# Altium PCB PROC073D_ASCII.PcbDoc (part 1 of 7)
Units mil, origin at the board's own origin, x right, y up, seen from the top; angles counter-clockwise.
Board outline 2165.35 x 2695.12 mil, 8 copper layers (Top Layer, L2_GND, L3_SIGNAL 1, L4_SIGNAL 2, L5_SIGNAL 3, L6_SIGNAL 4, L7_GND, Bottom Layer), stack 56.1 mil thick; 414 components, 319 nets, 1353 pads, 1669 vias.
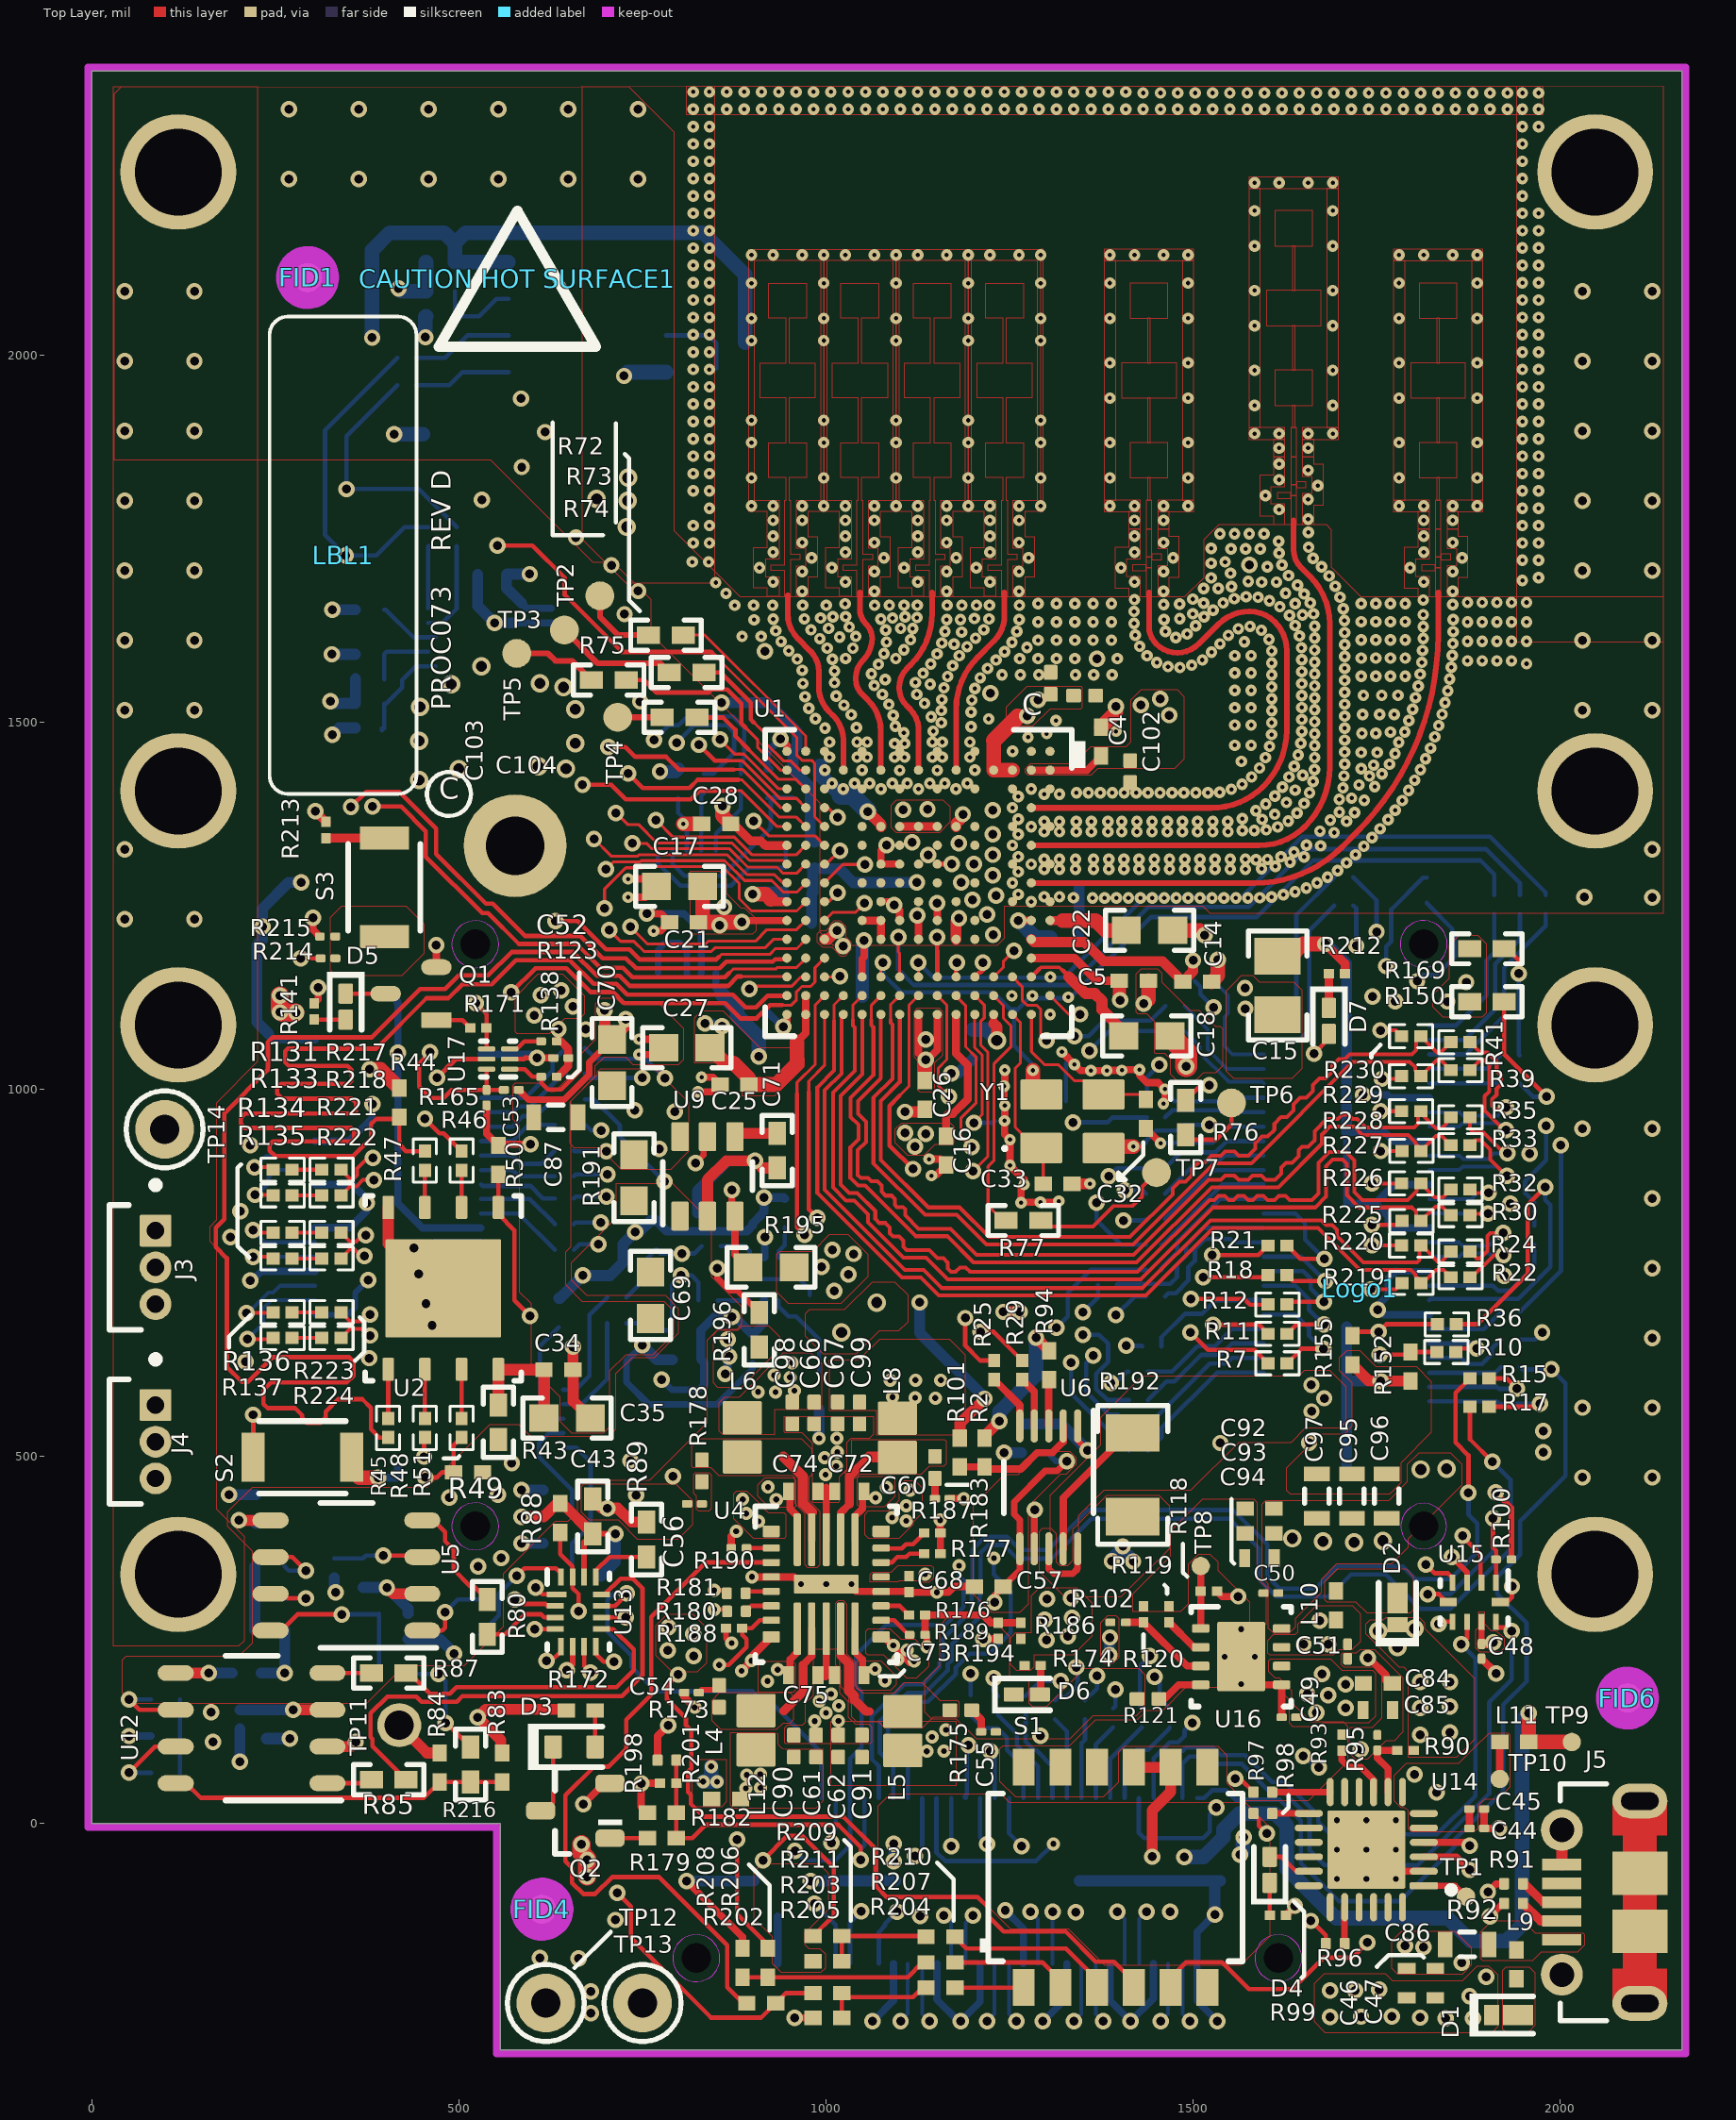
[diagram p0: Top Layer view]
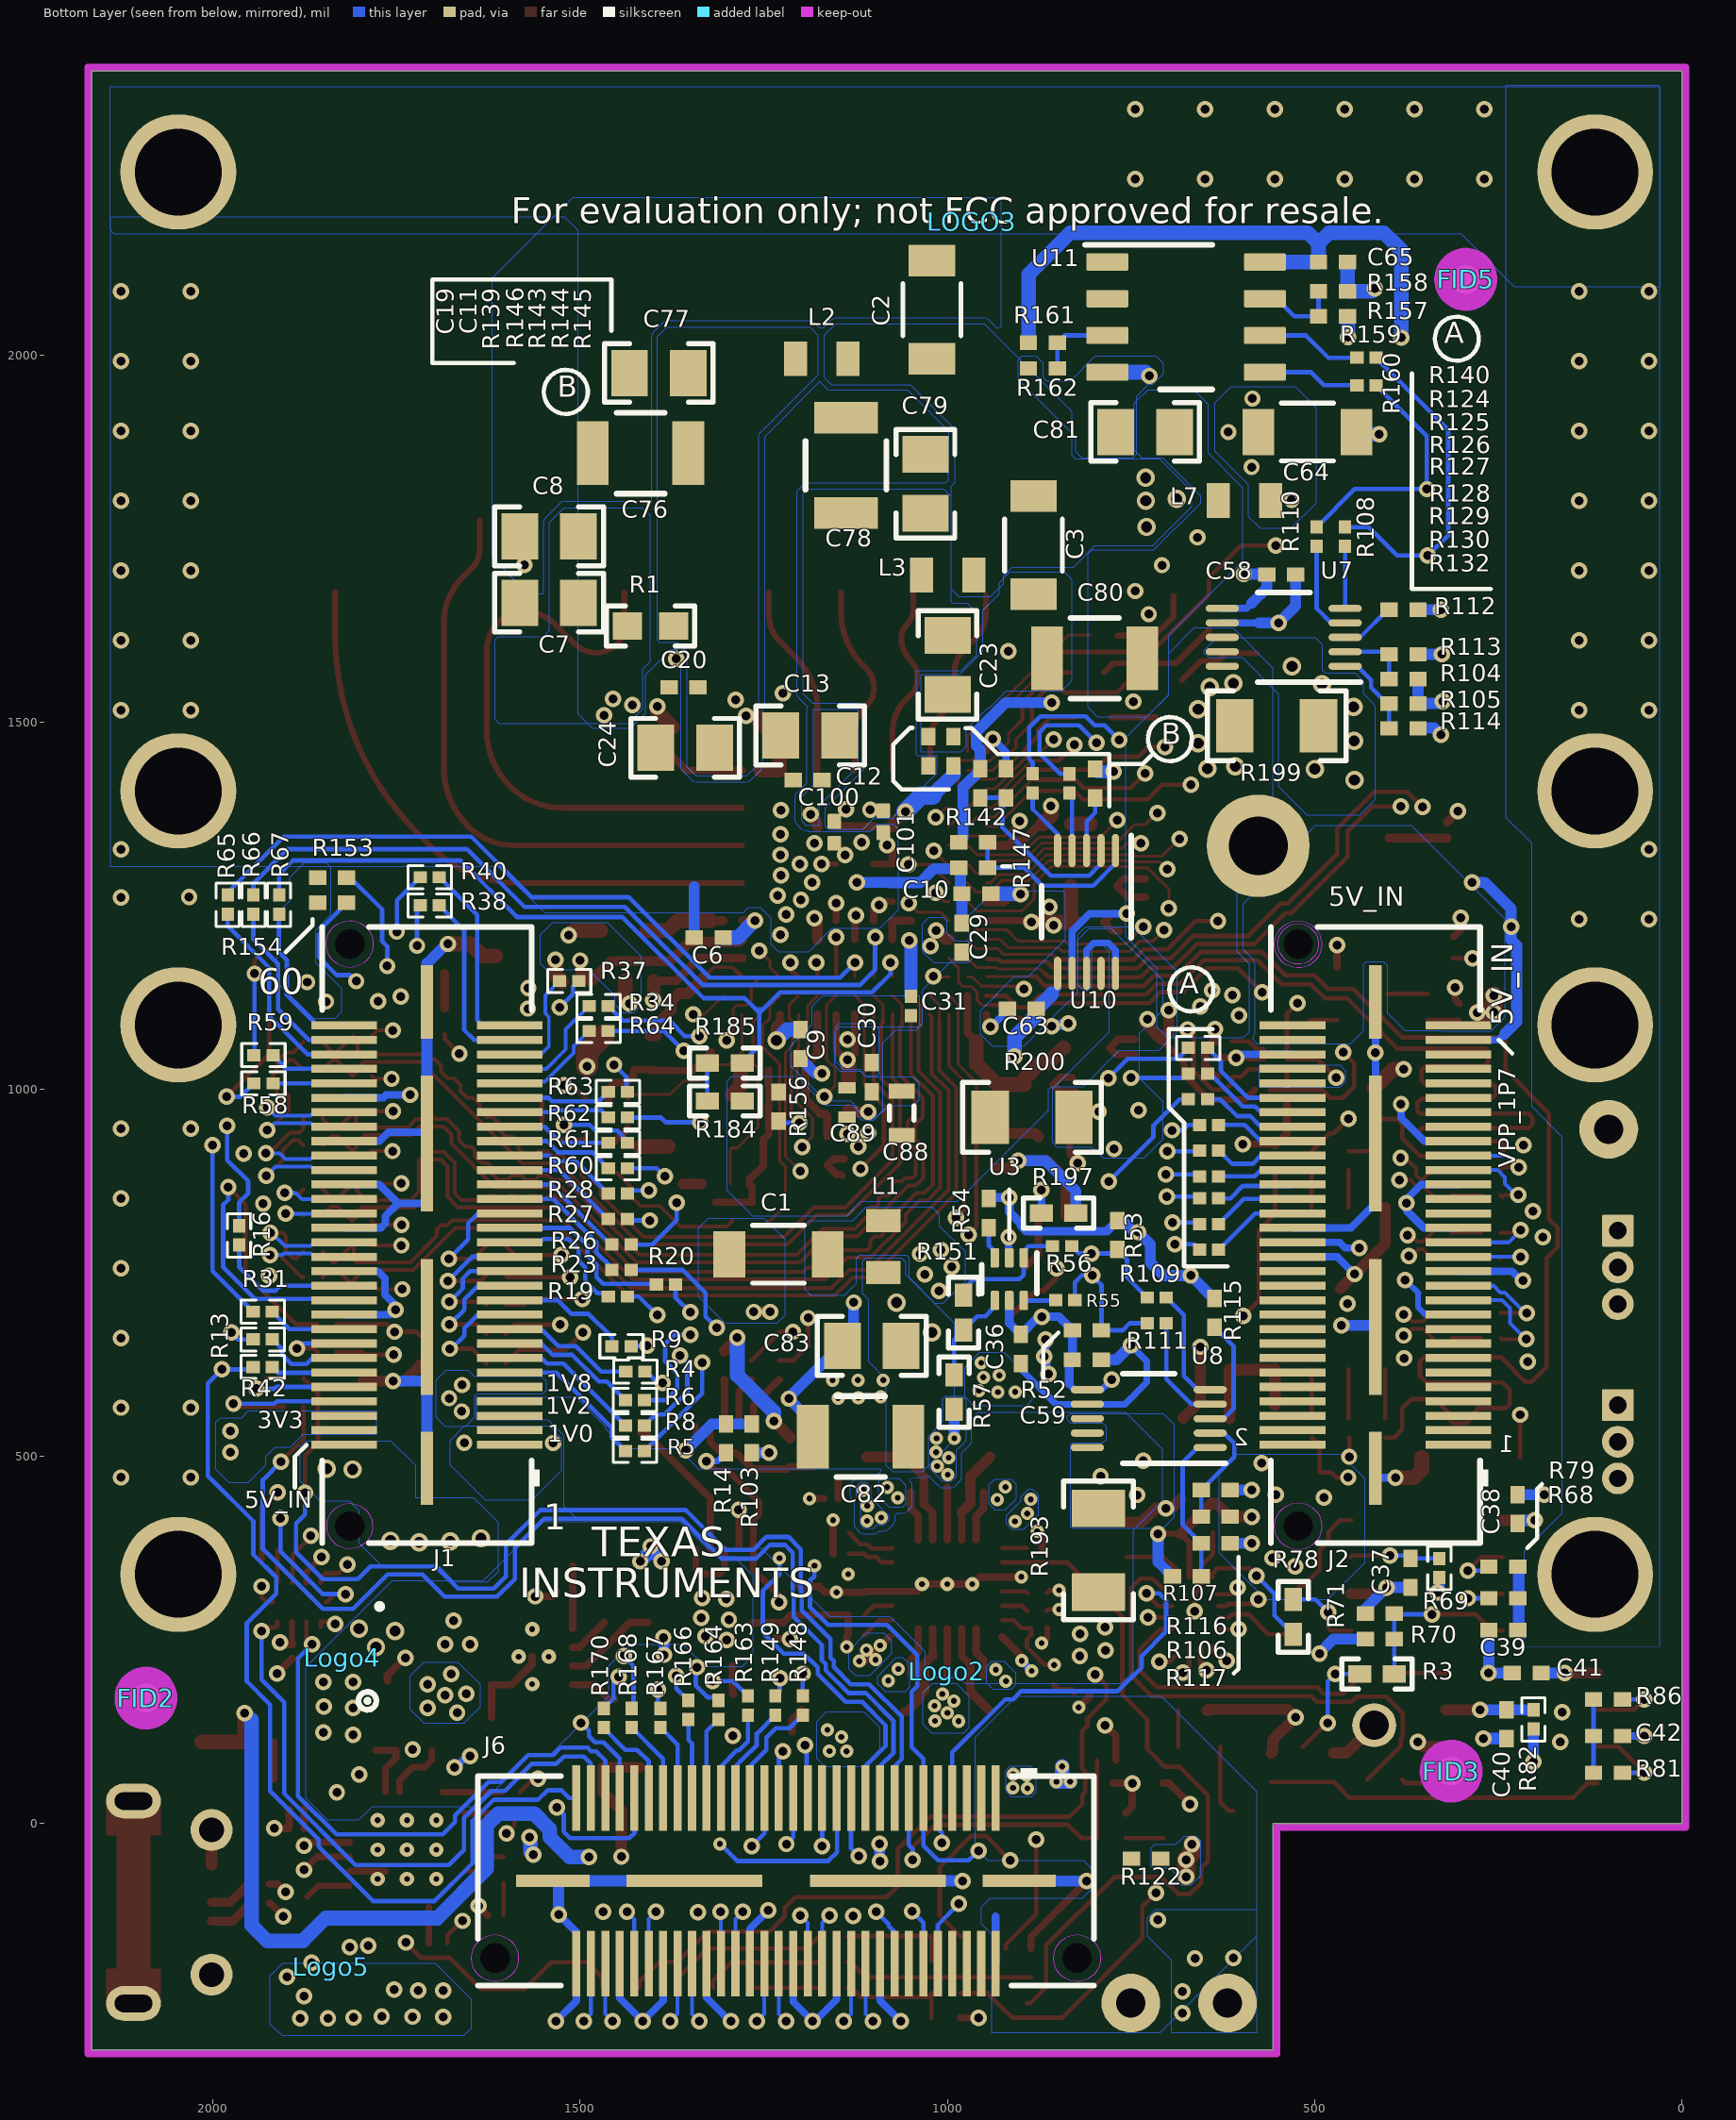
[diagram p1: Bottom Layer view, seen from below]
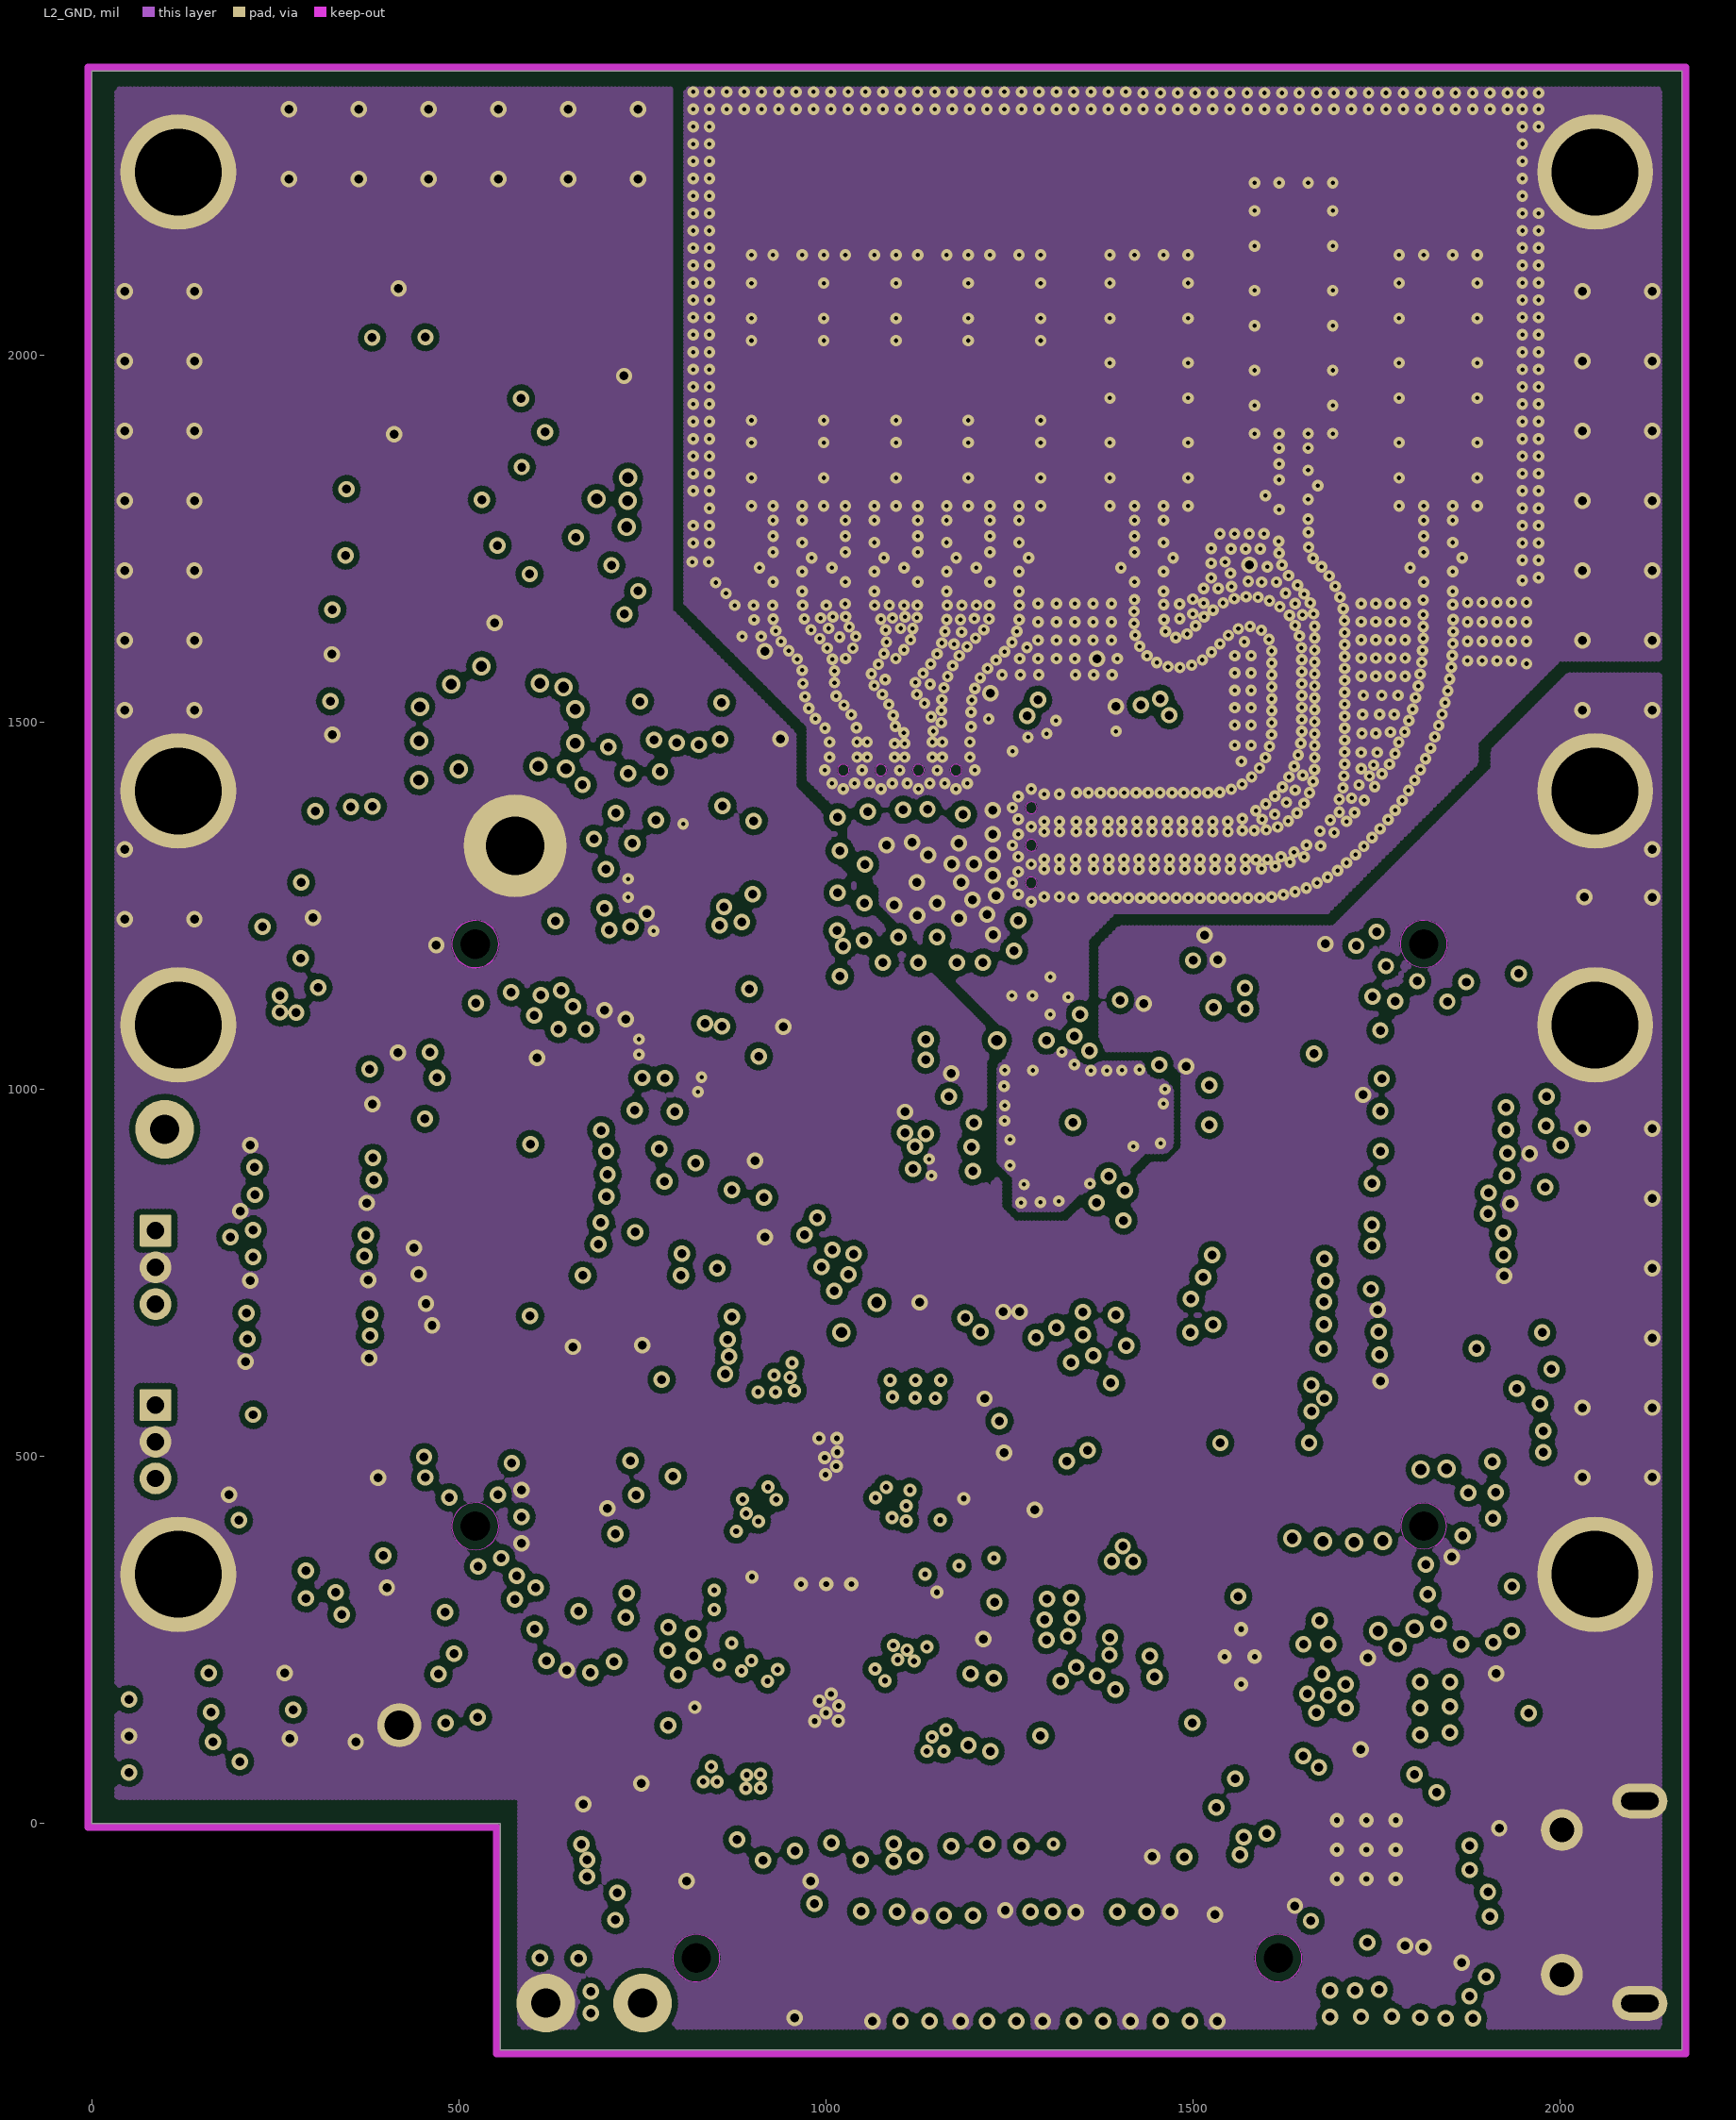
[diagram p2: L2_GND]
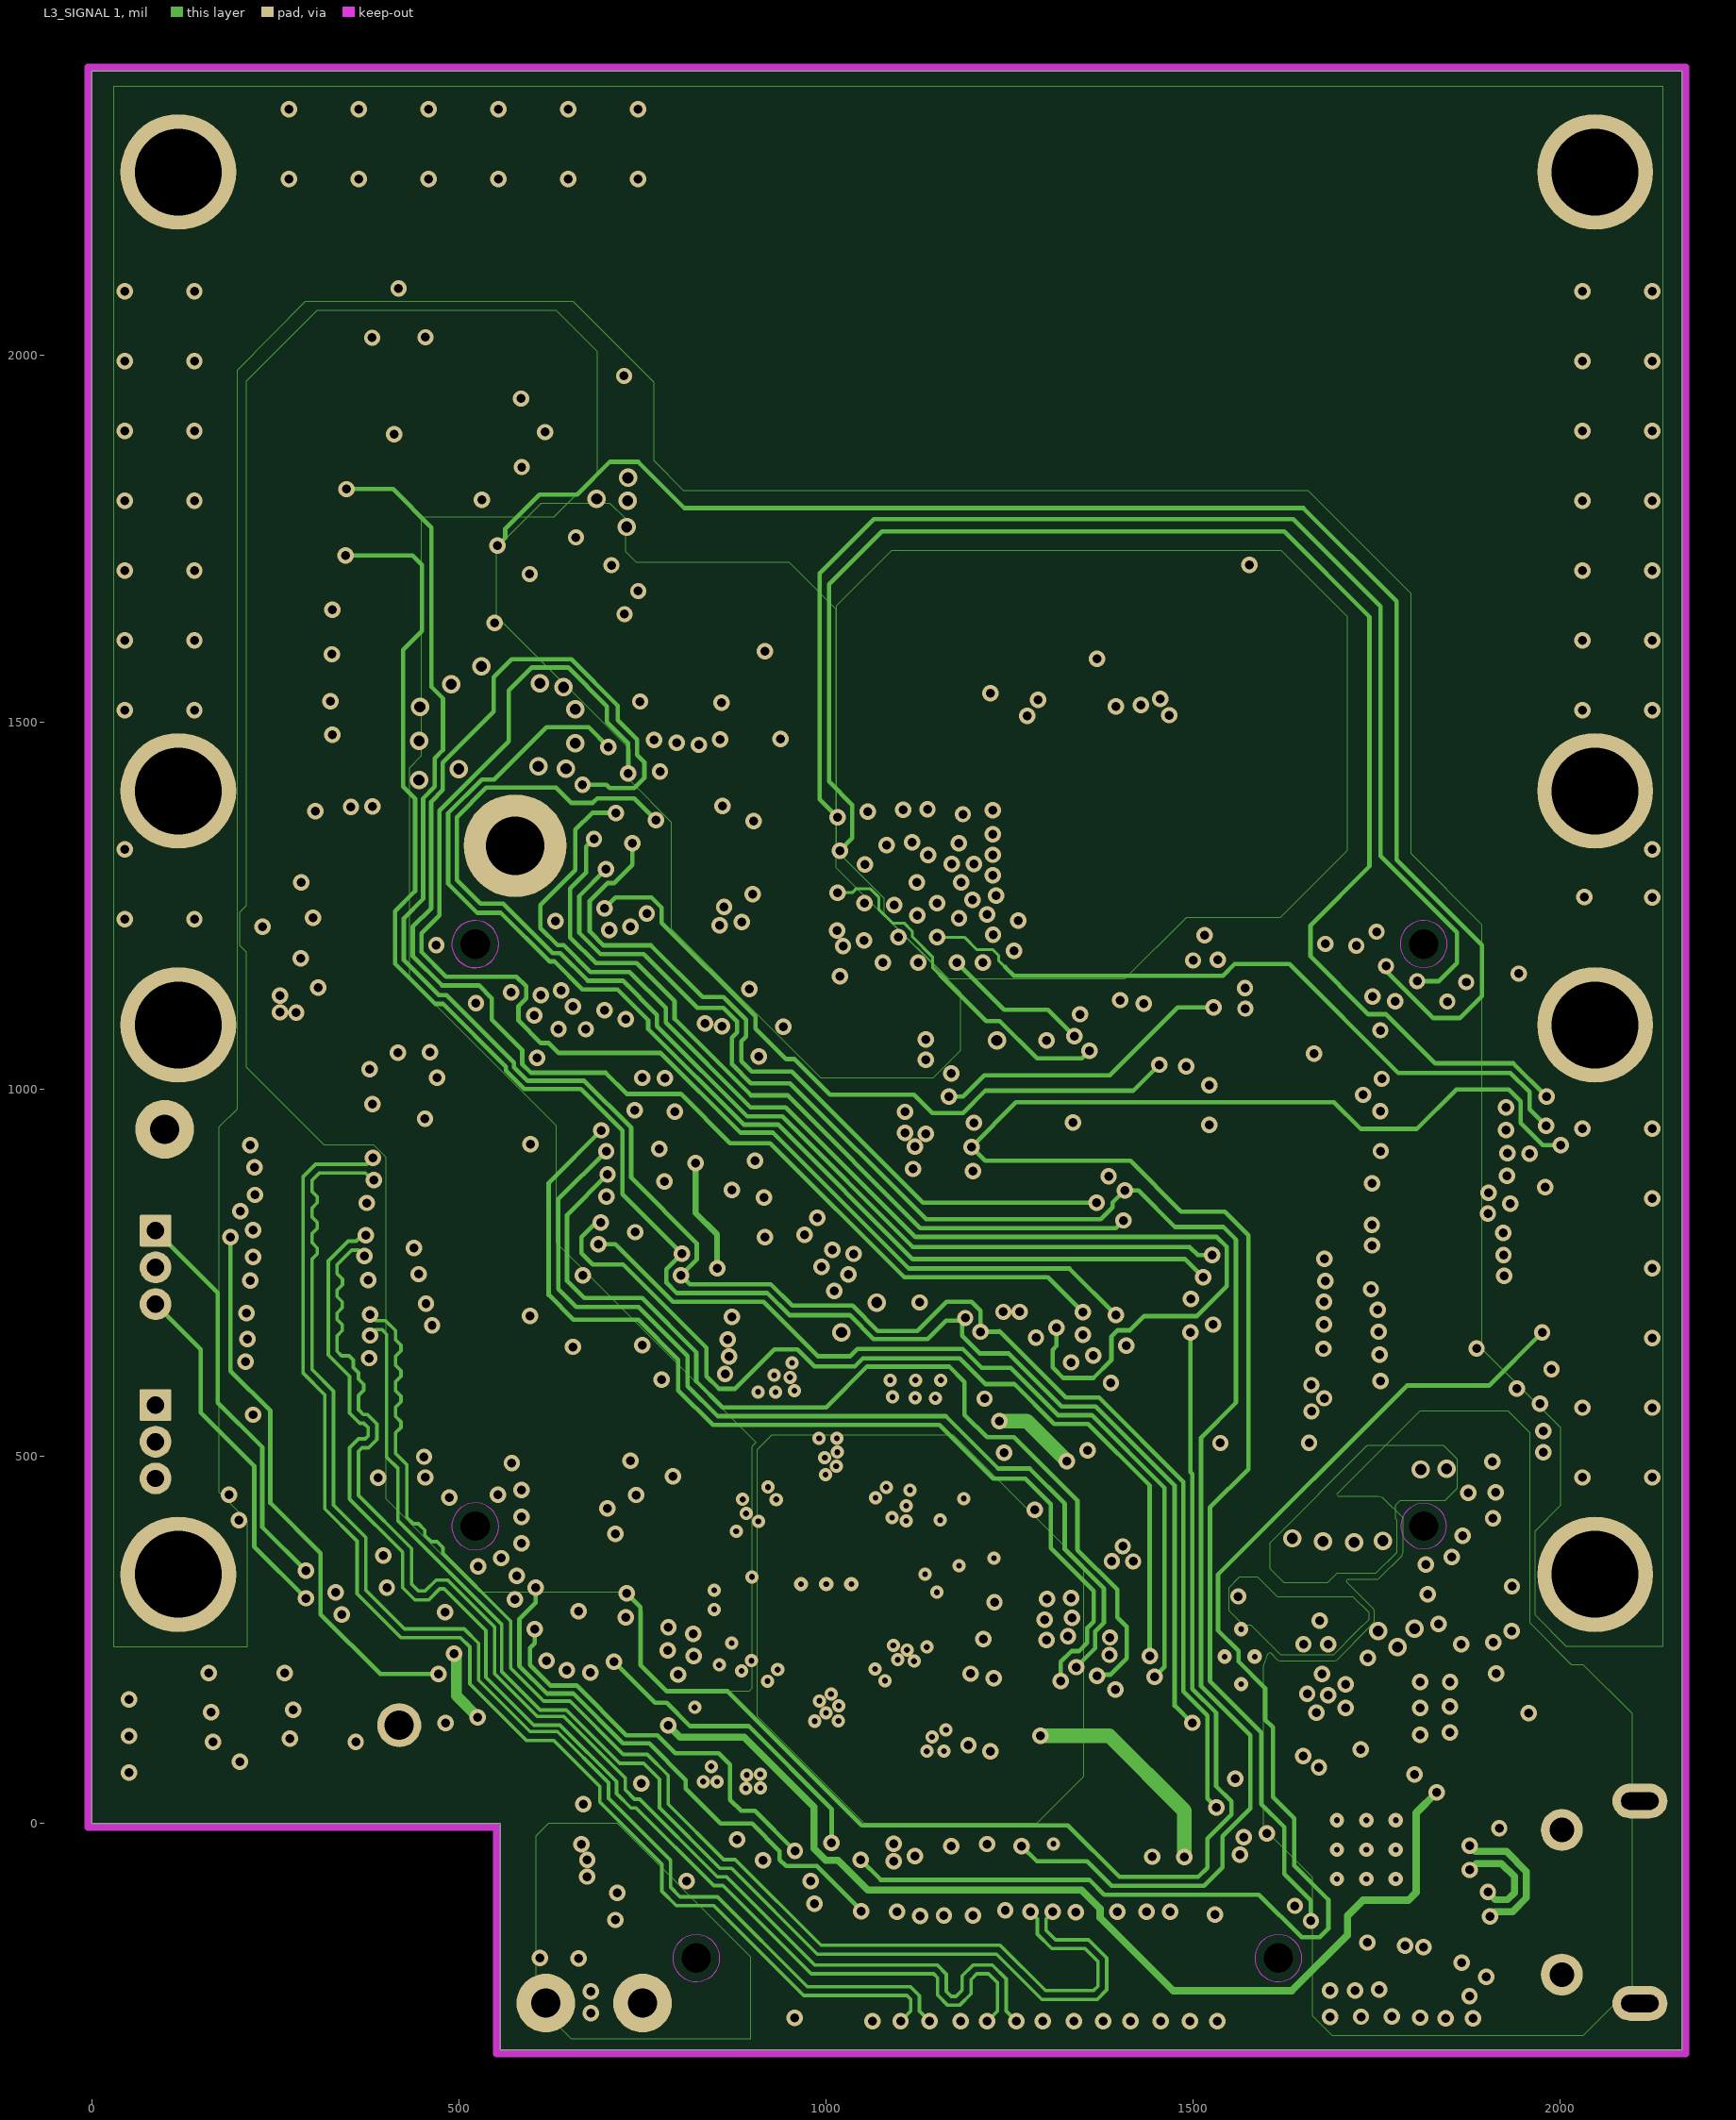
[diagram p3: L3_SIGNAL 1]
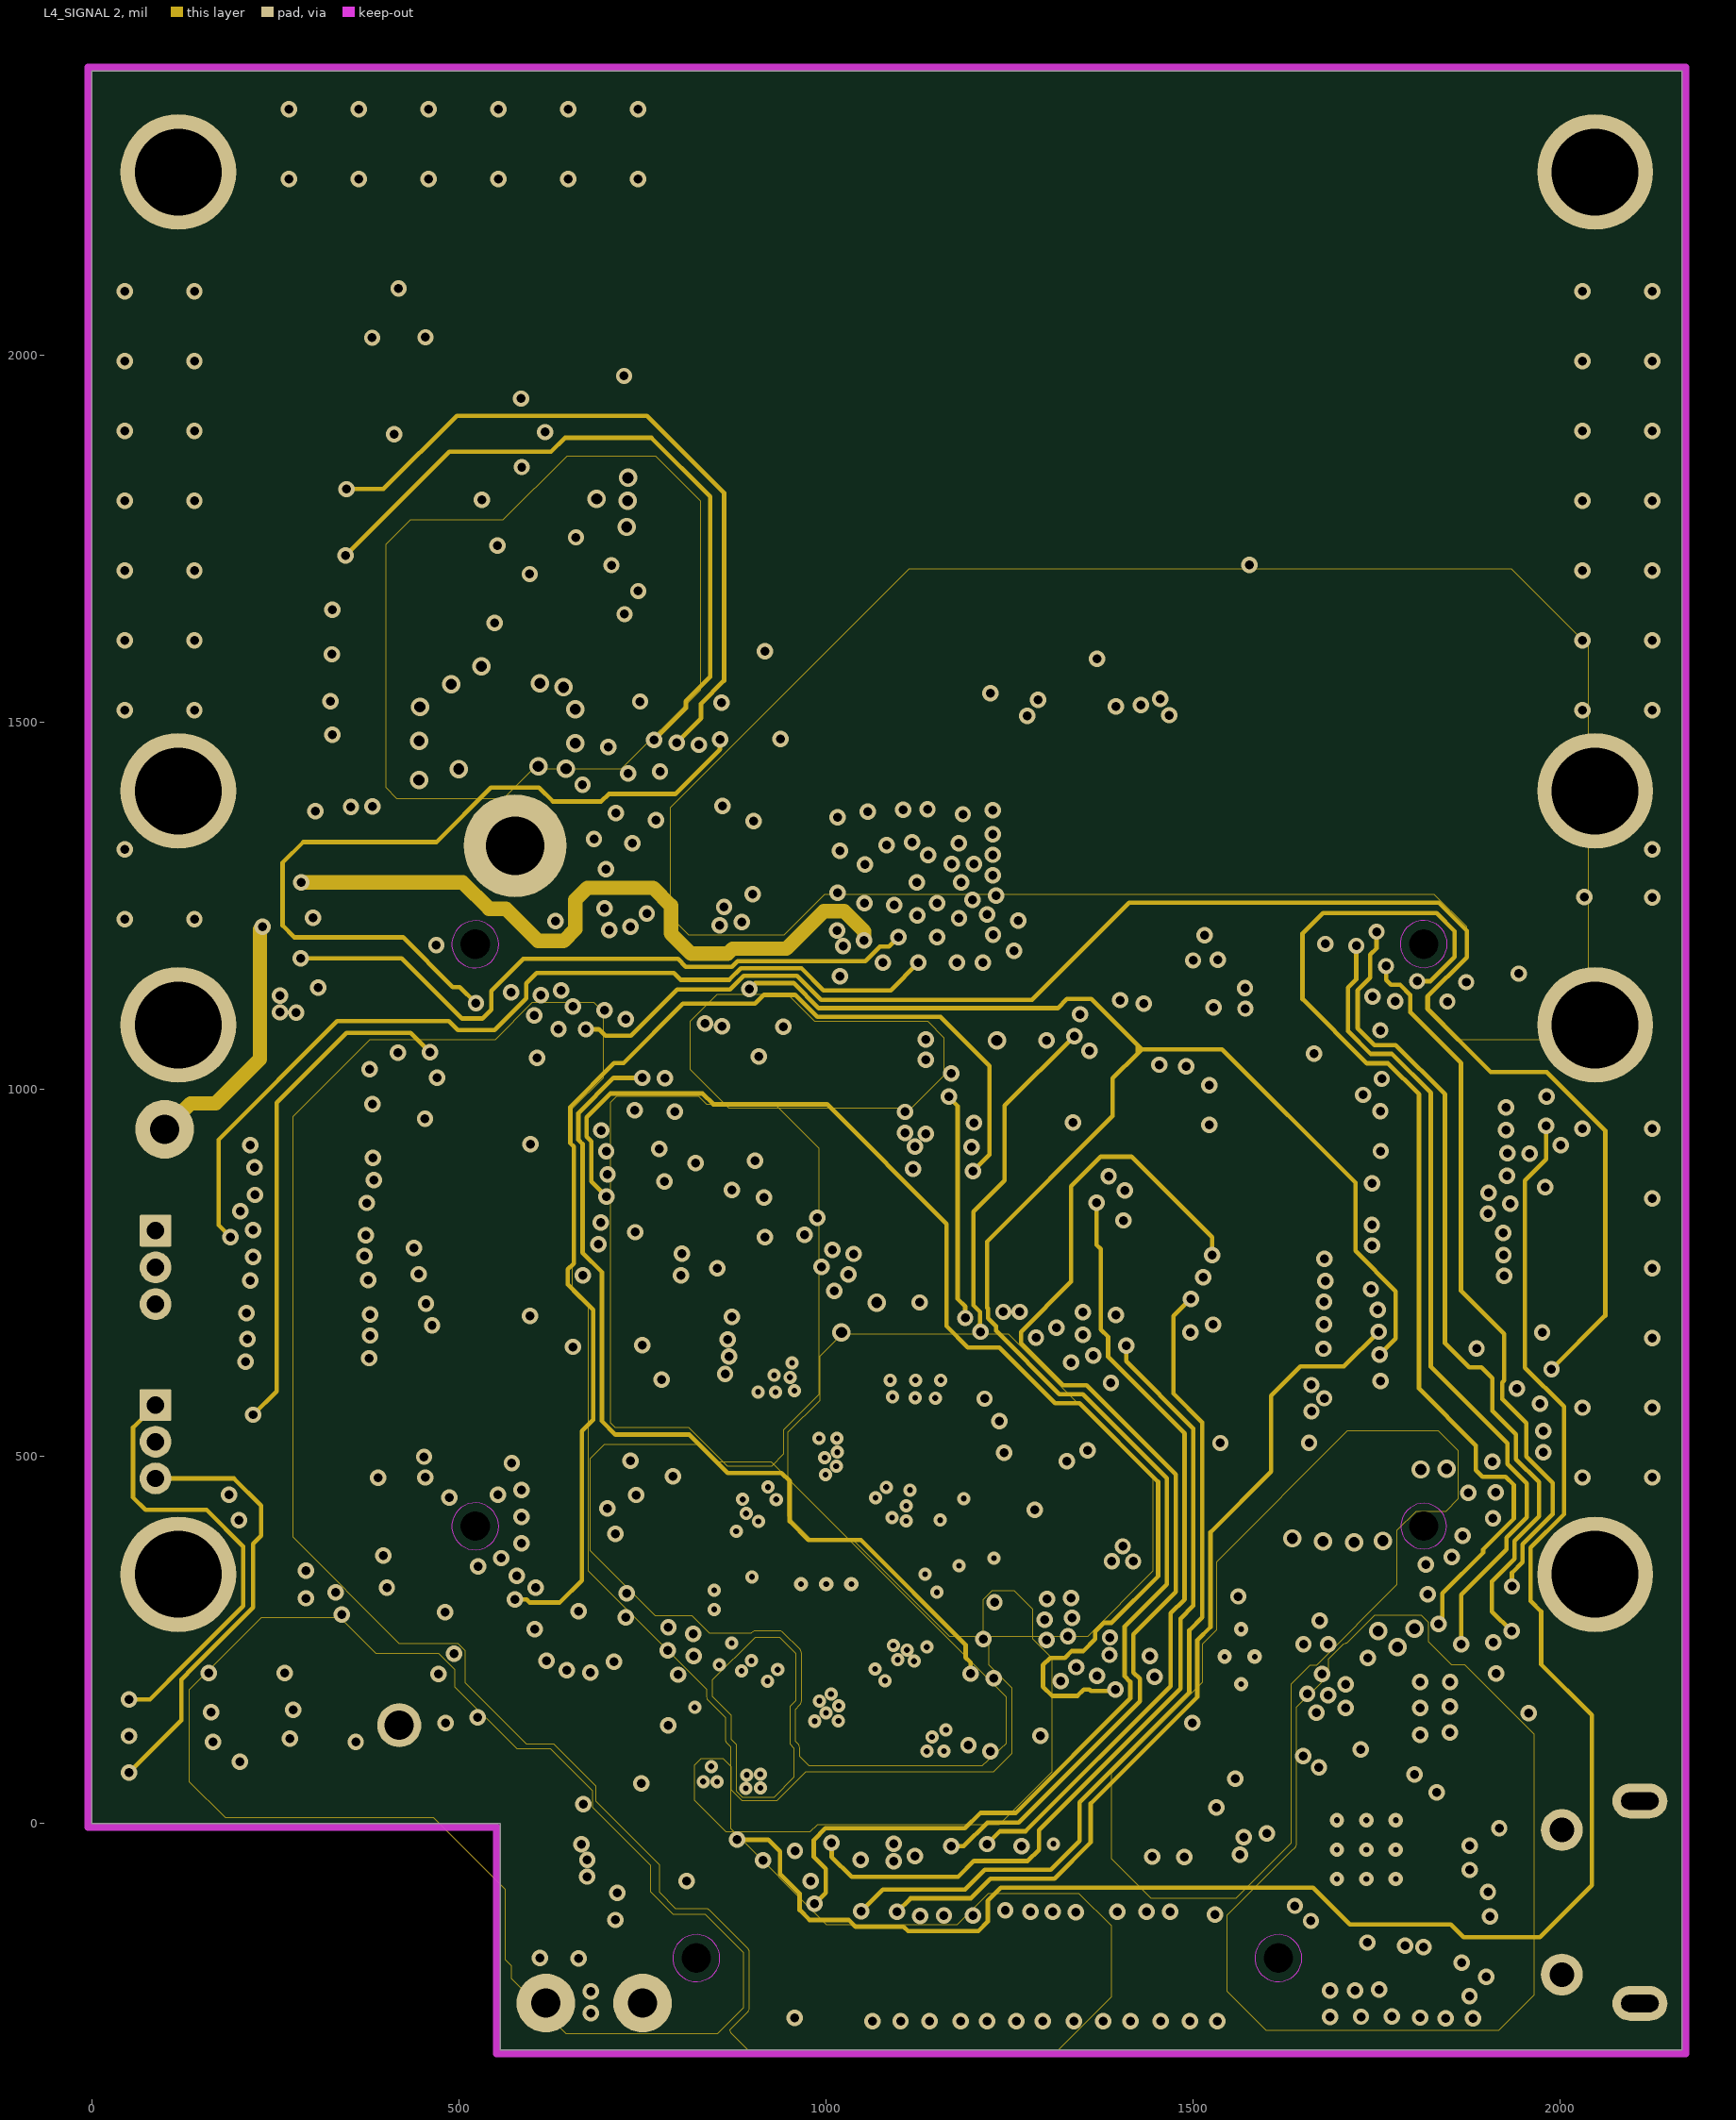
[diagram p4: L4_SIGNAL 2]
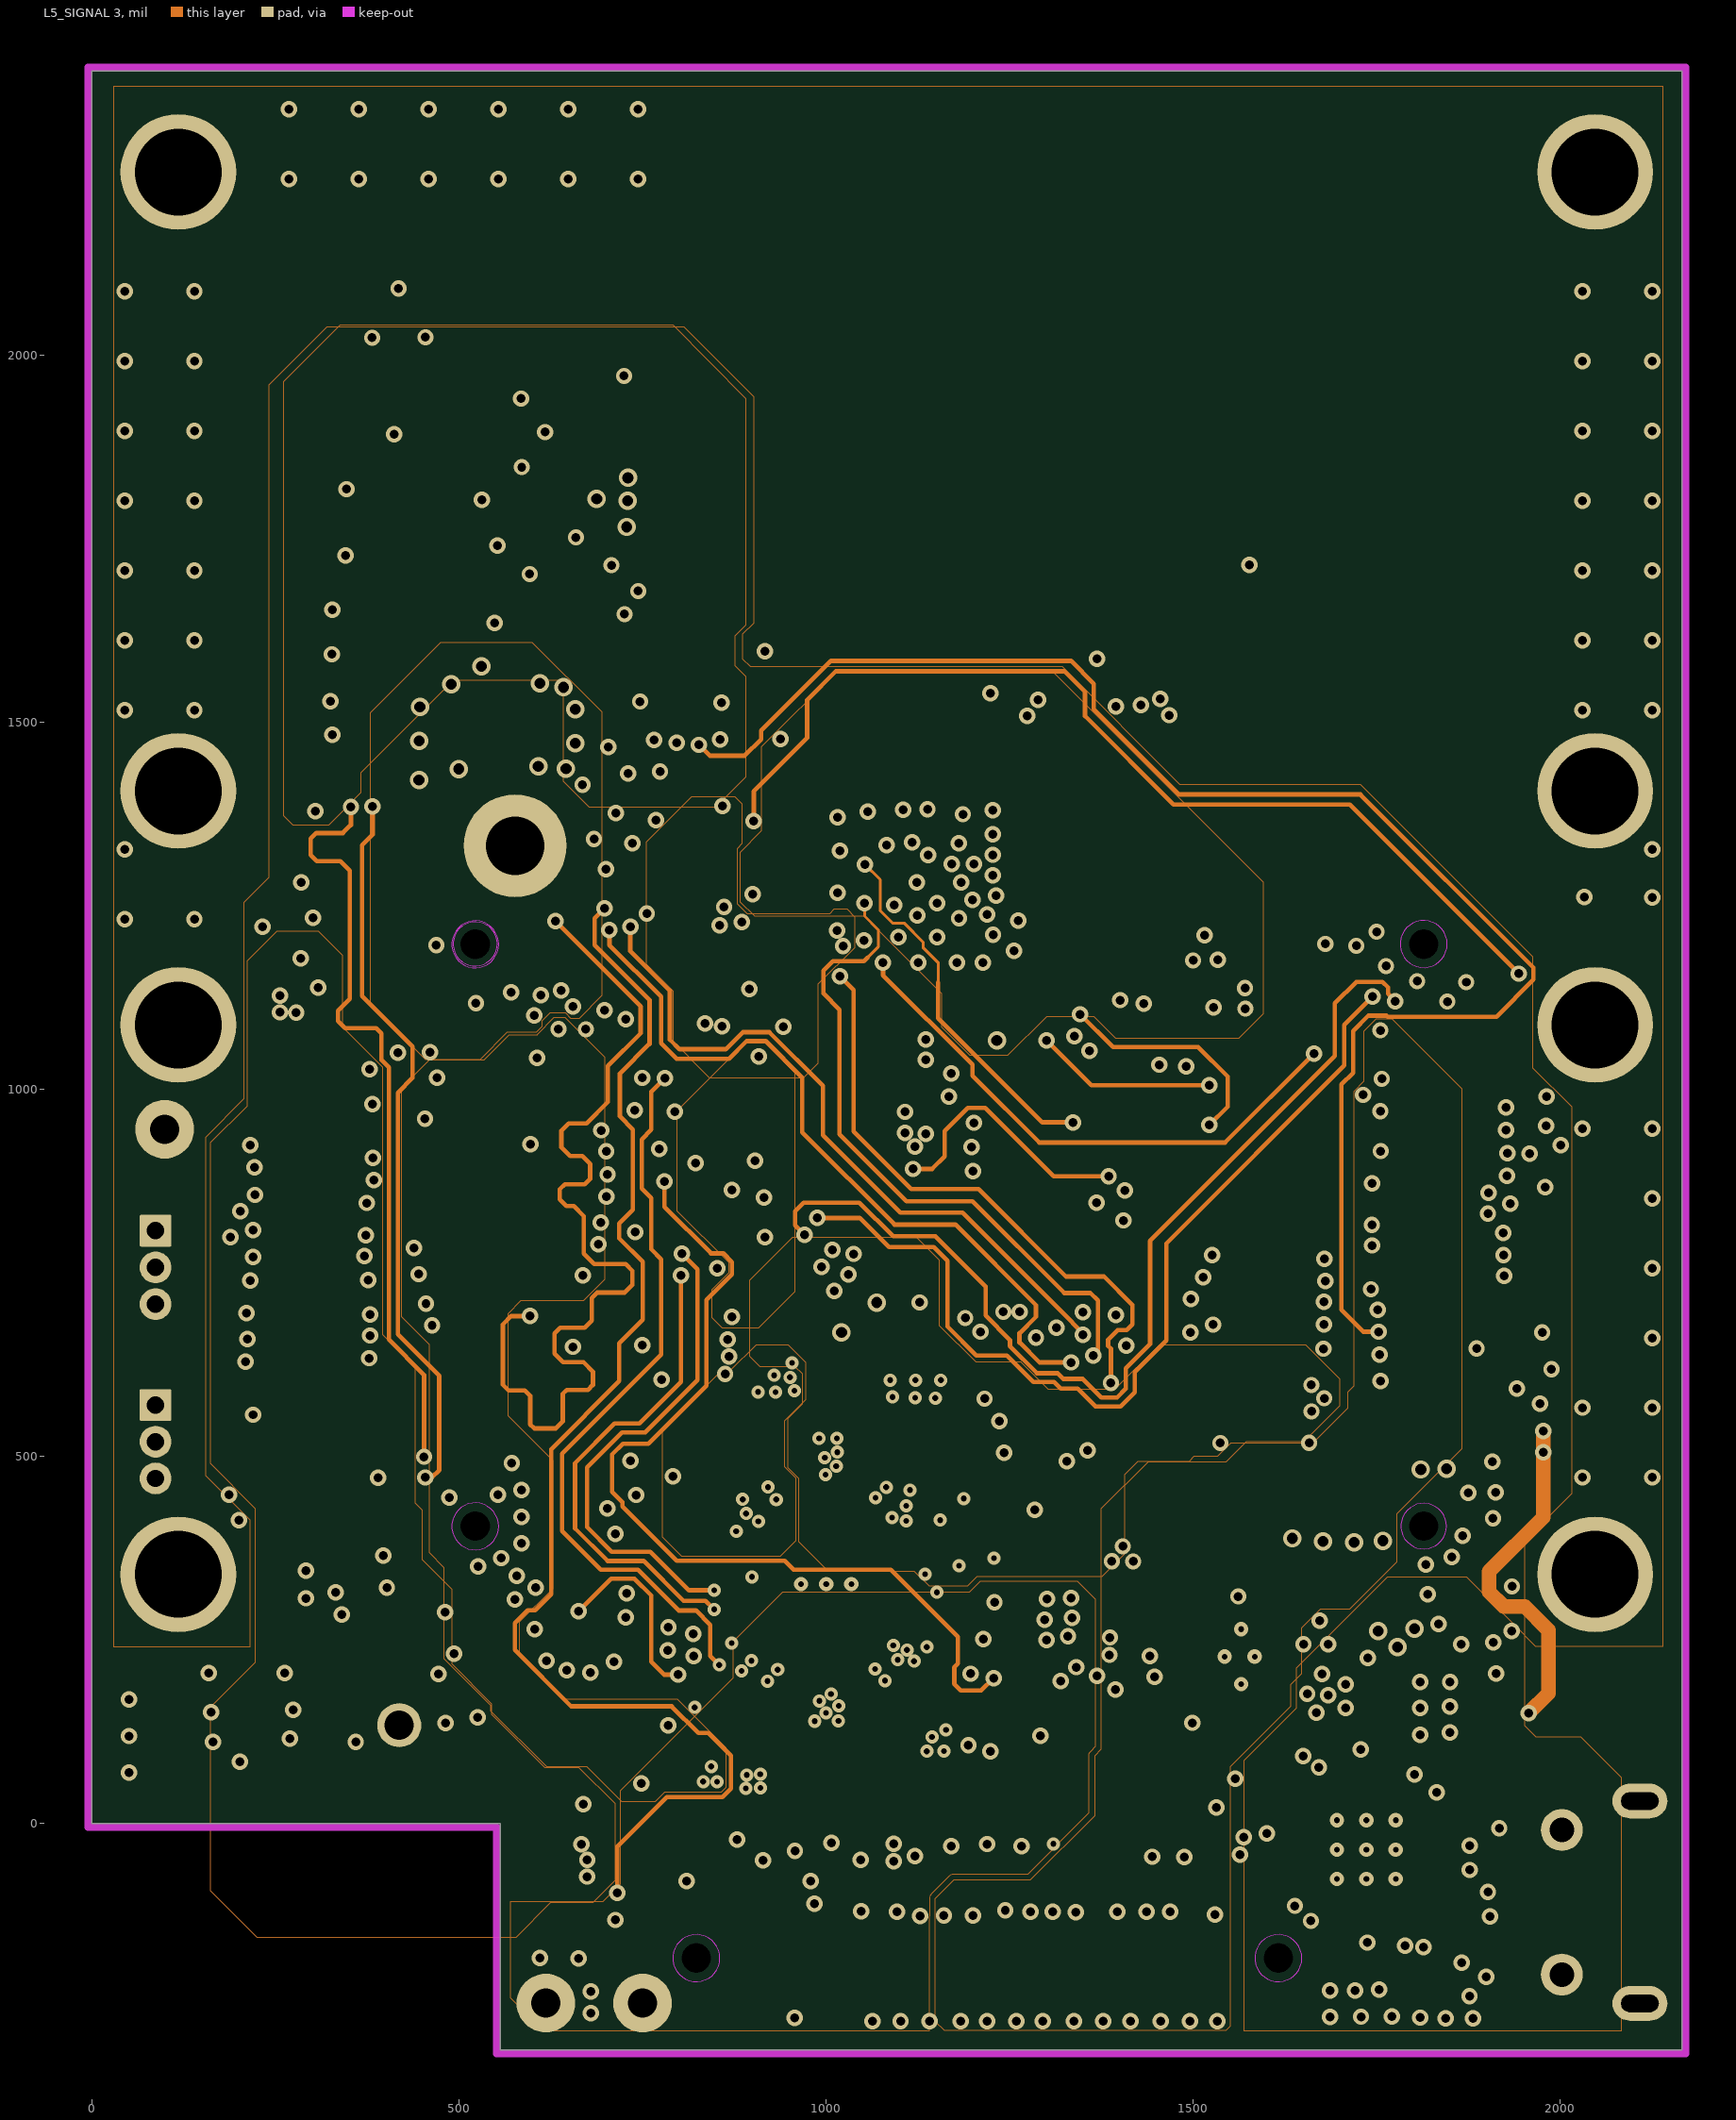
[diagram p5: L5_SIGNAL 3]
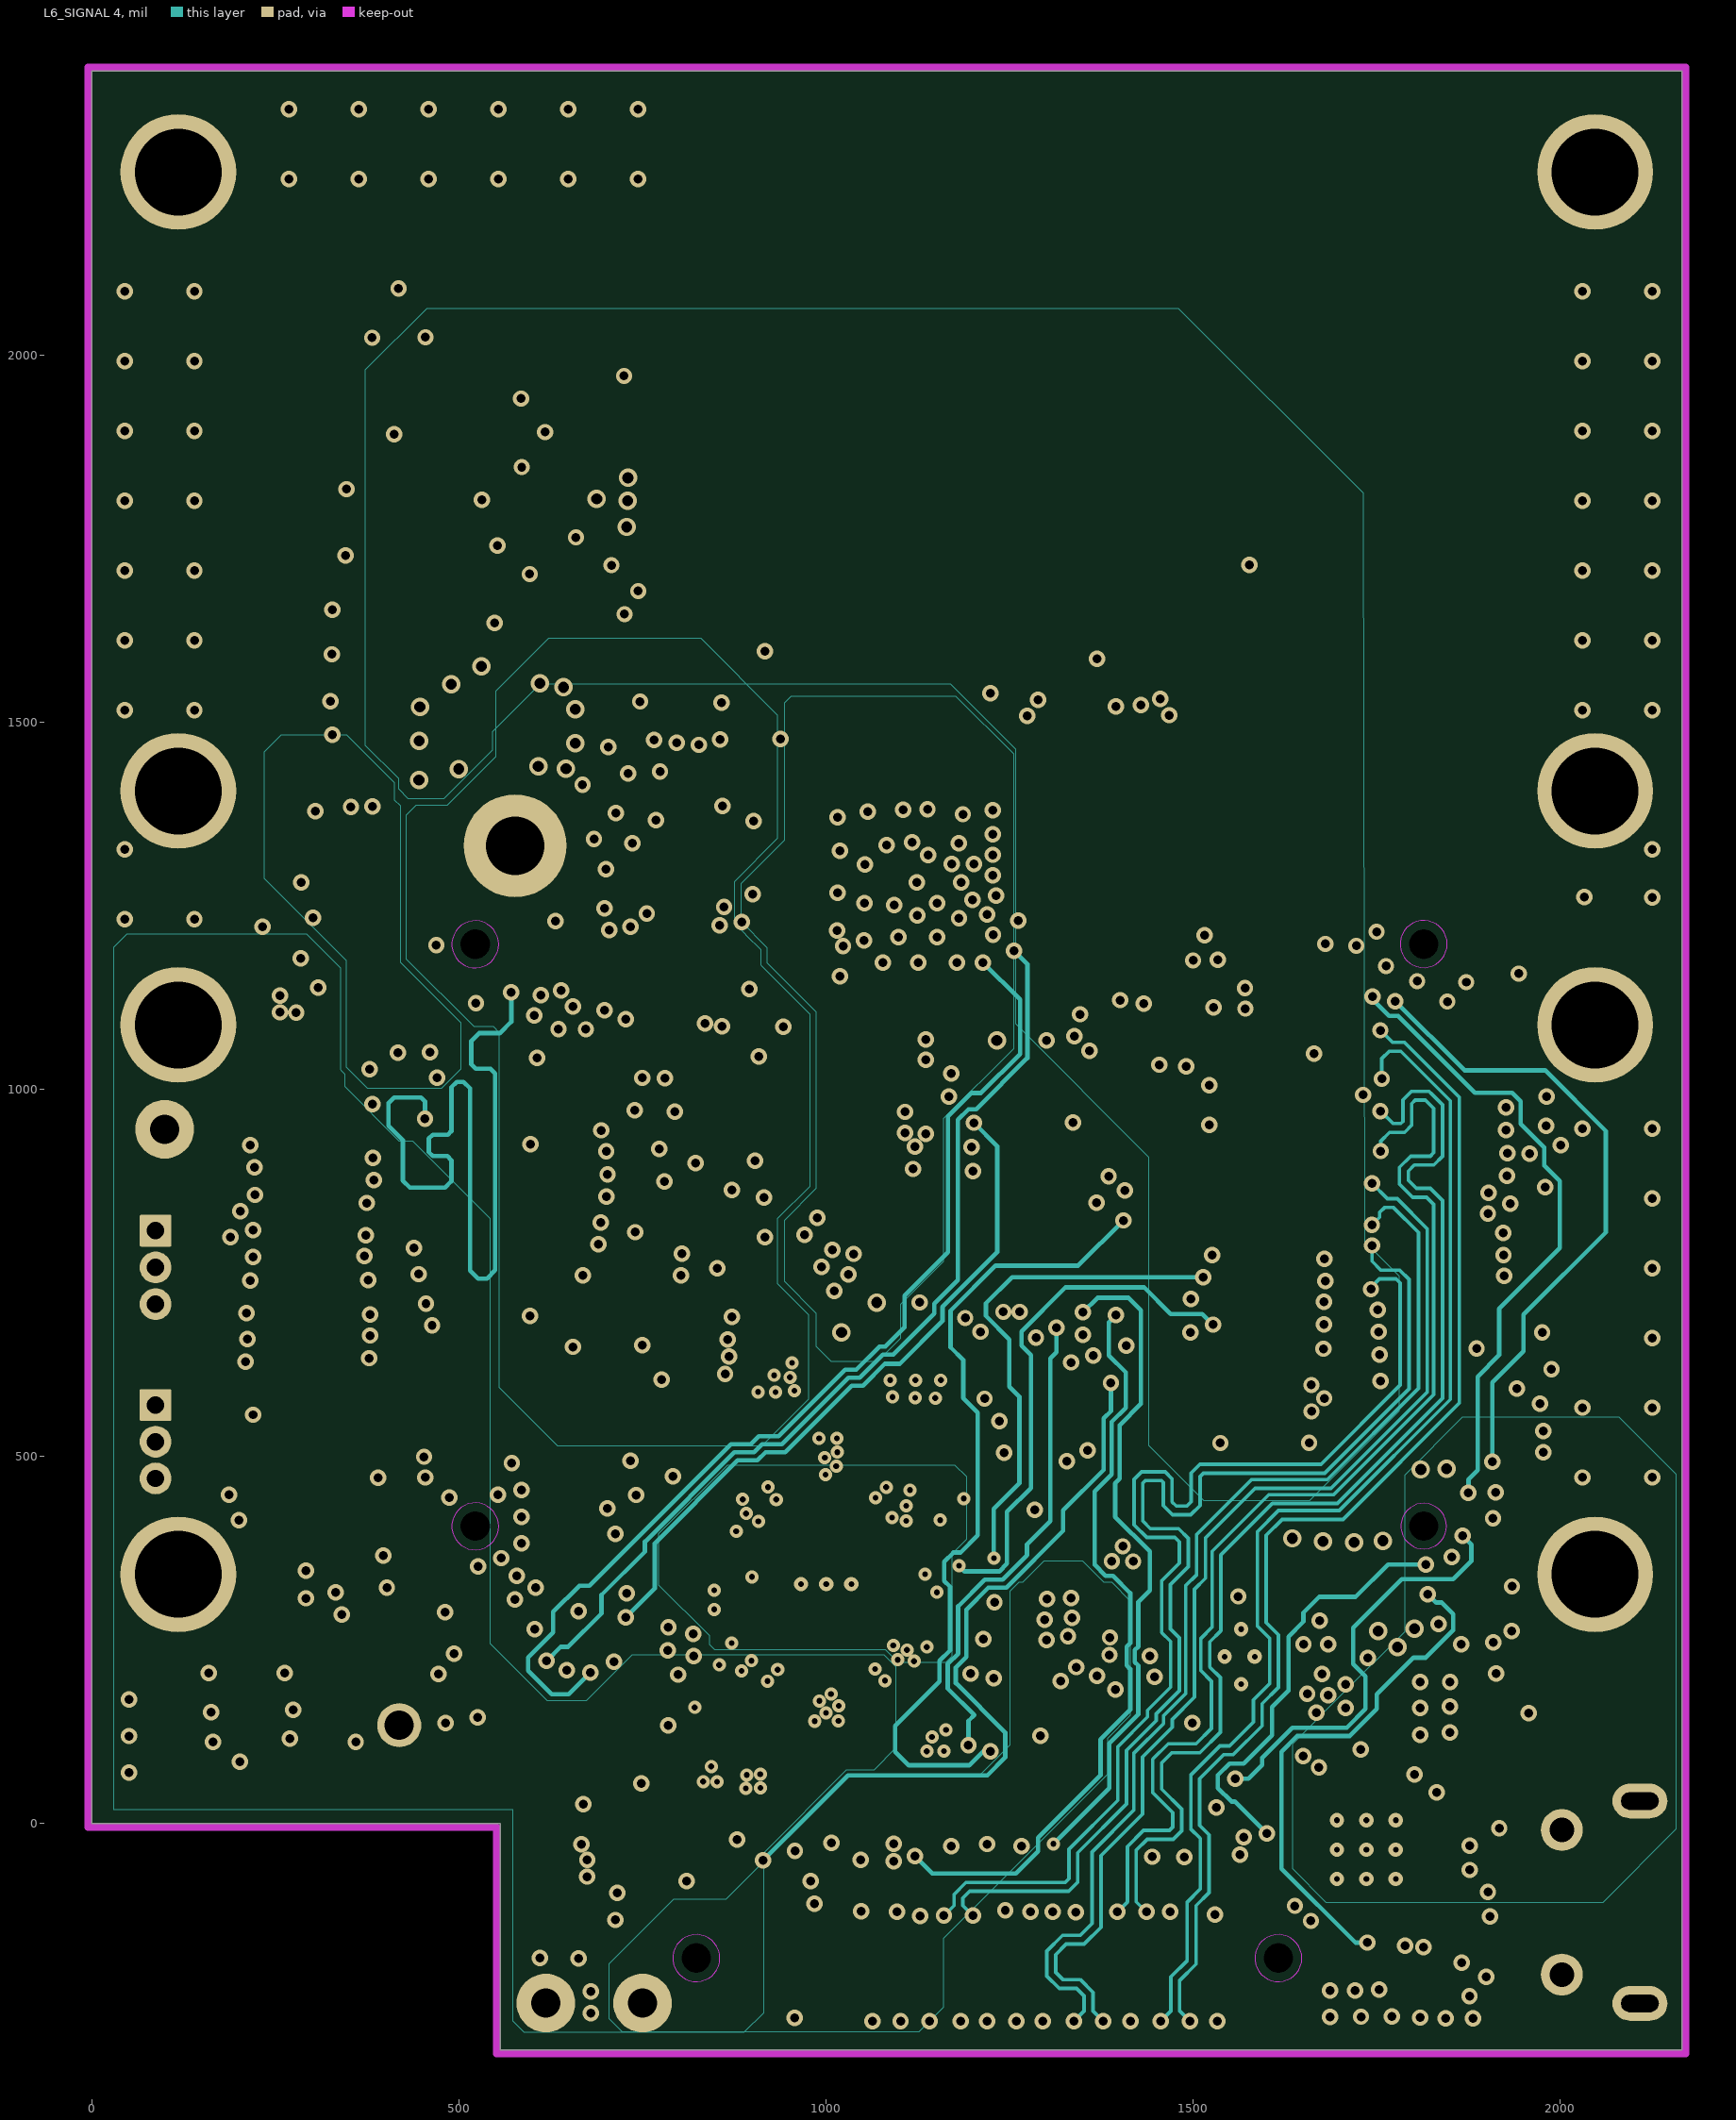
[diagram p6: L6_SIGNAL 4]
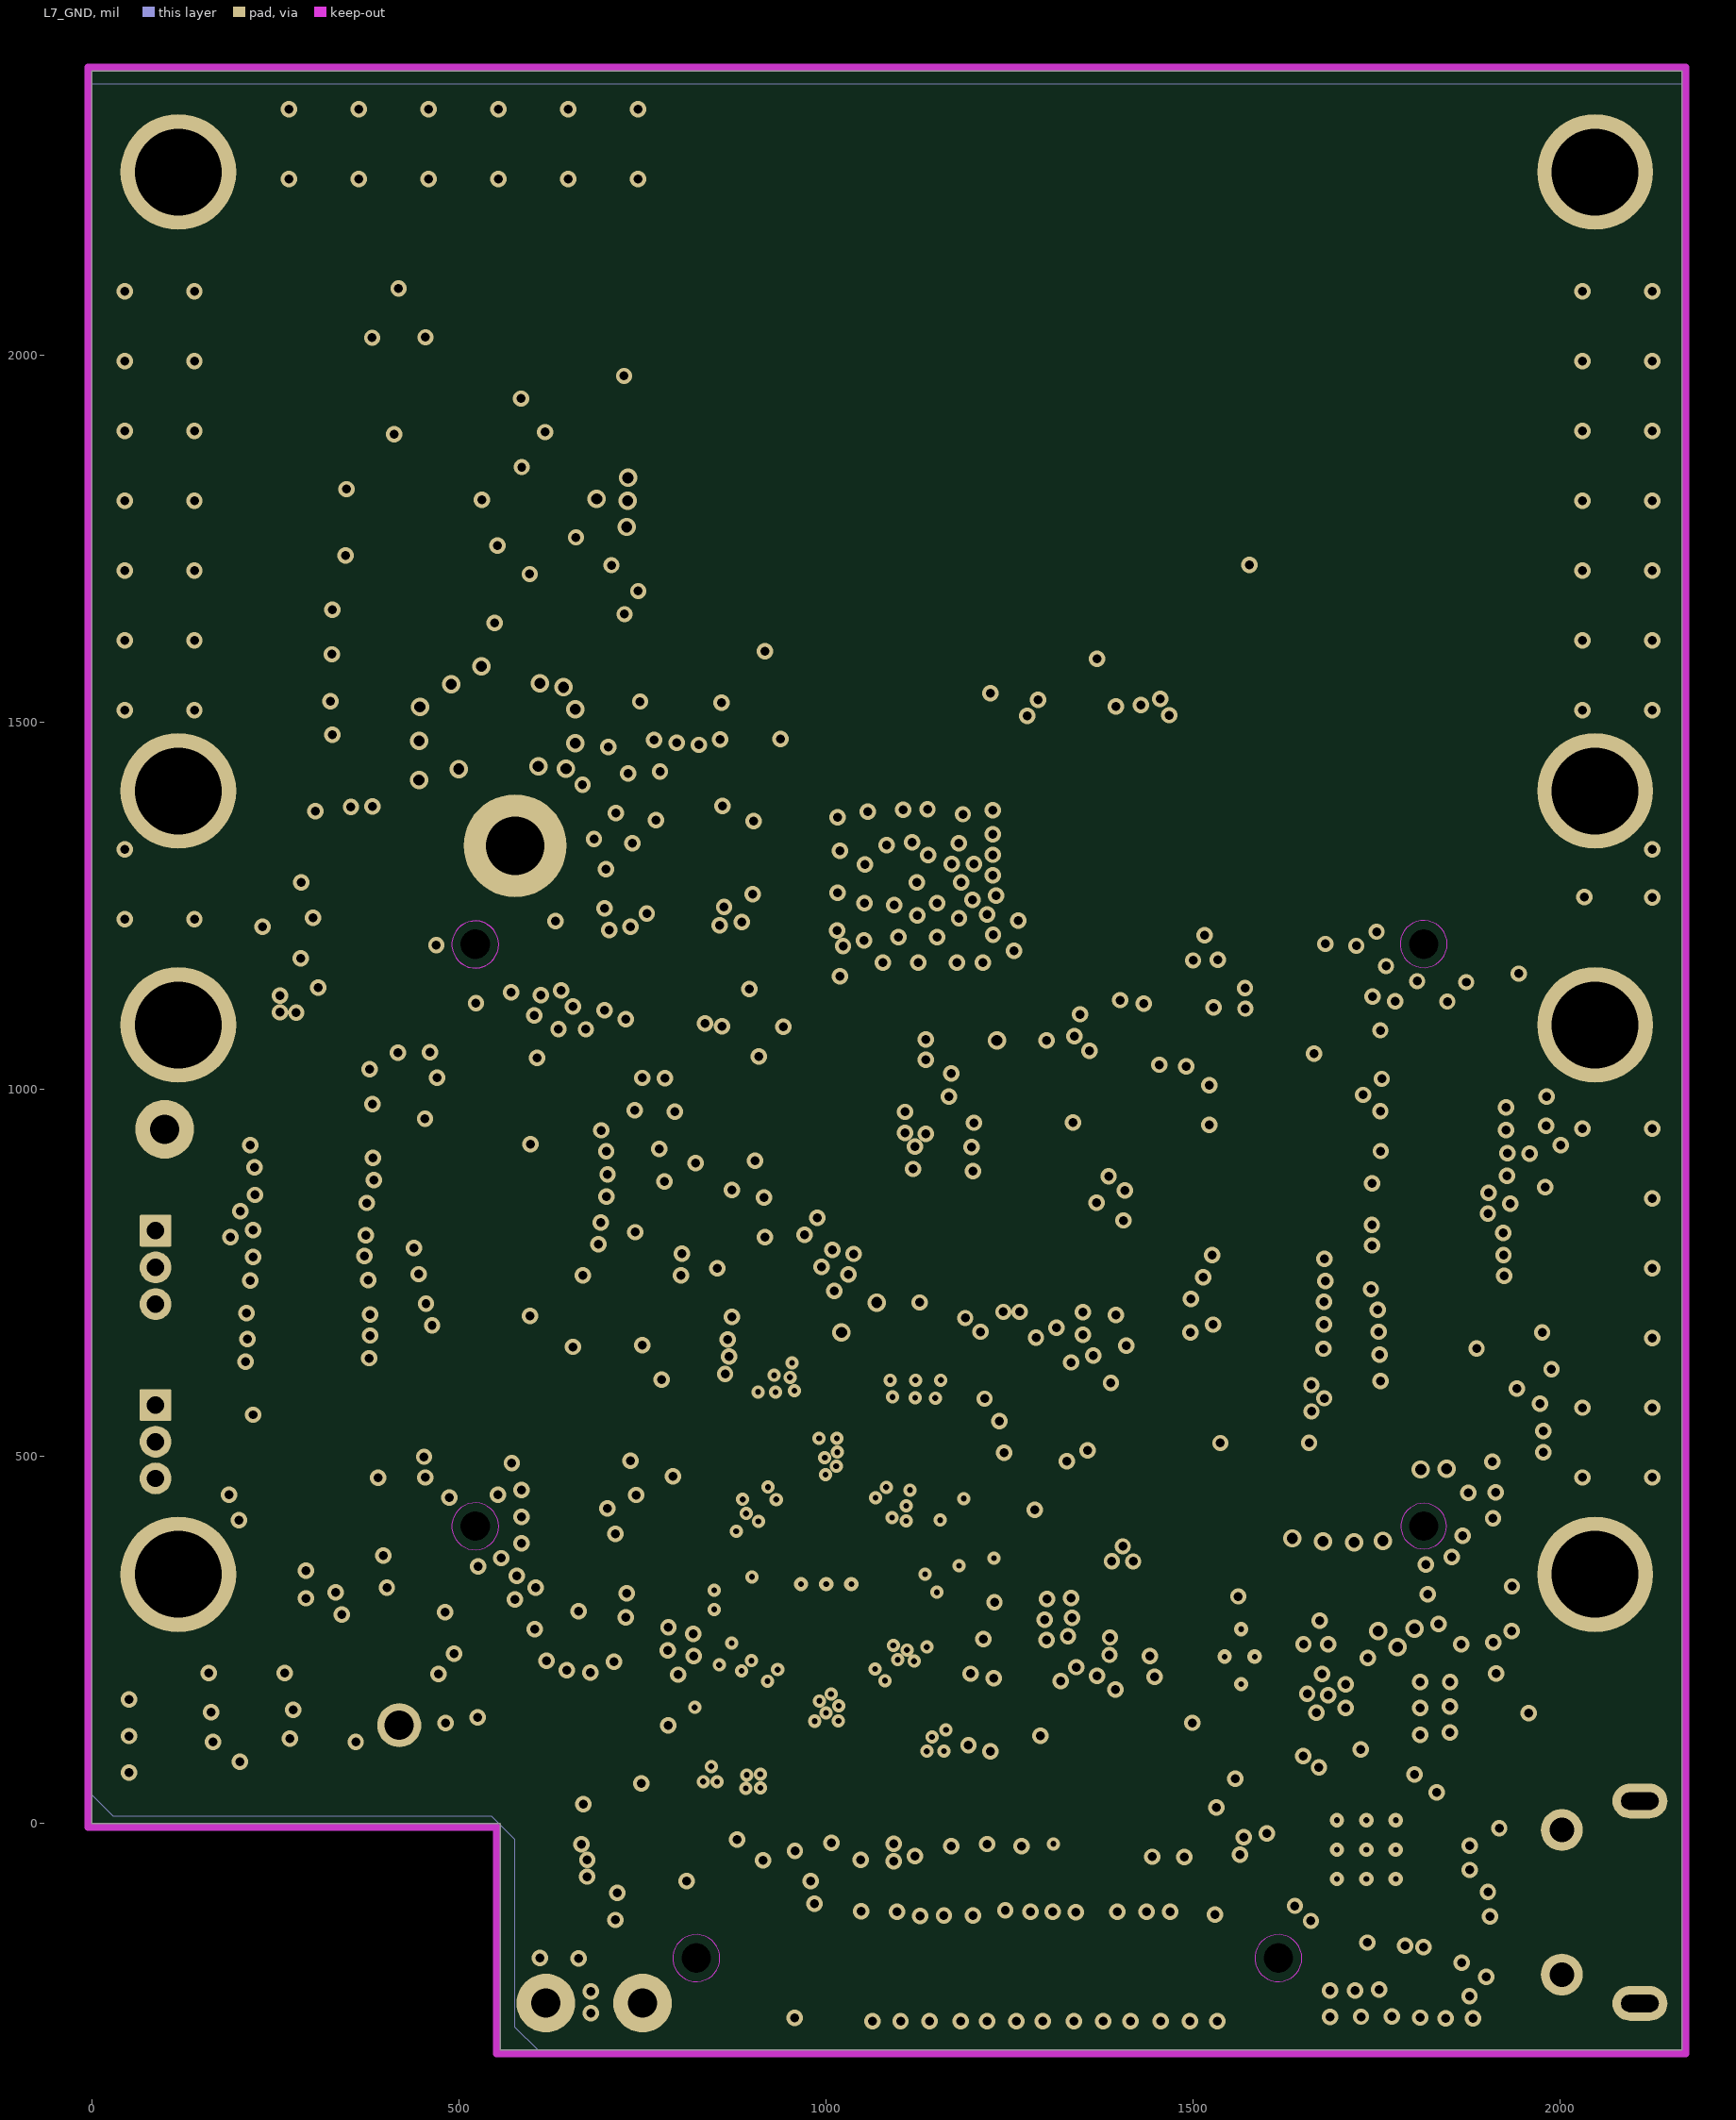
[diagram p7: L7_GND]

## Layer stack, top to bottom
Top Solder: solder mask 0.8, Solder Resist, Dk 1
Top Layer: signal copper 1.6
Dielectric 1: core 4, RO4835 LOPRO, Dk 3.5
L2_GND: signal copper 1.4
Dielectric 2: prepreg 5.5, PCL370HR, Dk 4.17
L3_SIGNAL 1: signal copper 1.4
Dielectric 3: core 10, PCL370HR, Dk 4.17
L4_SIGNAL 2: signal copper 1.4
Dielectric 4: prepreg 5.5, PCL370HR, Dk 4.17
L5_SIGNAL 3: signal copper 1.4
Dielectric 5: prepreg 10, PCL370HR, Dk 4.17
L6_SIGNAL 4: signal copper 1.4
Dielectric 6: core 5.5, PCL370HR, Dk 4.17
L7_GND: signal copper 1.4
Dielectric 7: core 4, PCL370HR, Dk 4.17
Bottom Layer: signal copper 1.6
Bottom Solder: solder mask 0.8, Solder Resist, Dk 1

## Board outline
0,0 556.54,0 556.54,-308.34 2165.35,-308.34 2165.35,2386.78 0,2386.78

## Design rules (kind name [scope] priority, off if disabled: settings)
AcuteAngle [All] p0 off: scope1count=1 scope1_0_kind=Board scope1_0_value=Board scope2count=1 scope2_0_kind=Board scope2_0_value=Board commentlength=0 minimum=4.50000000000000E+0001
AcuteAngle [All] p1 off: minimum=4.50000000000000E+0001 checktracksonly=FALSE
AssemblyTestPointUsage [All] p0: scope1count=1 scope1_0_kind=Board scope1_0_value=Board scope2count=1 scope2_0_kind=Board scope2_0_value=Board commentlength=0
AssemblyTestPointUsage [All] p1: valid=2
AssemblyTestpoint [All] p0: scope1count=1 scope1_0_kind=Board scope1_0_value=Board scope2count=1 scope2_0_kind=Board scope2_0_value=Board commentlength=0
Clearance Clearance_KO [All] p0 off: scope1count=1 scope1_0_kind=Board scope1_0_value=Board scope2count=1 scope2_0_kind=Board scope2_0_value=Board commentlength=47 gap=1 // Protel DXP Scope 2 Expression Was: IsSMTPin
Clearance Clearance_KO-J5 [All] p0 off: scope1count=1 scope1_0_kind=Board scope1_0_value=Board scope2count=1 scope2_0_kind=Component scope2_0_value=J5 commentlength=60 gap=19.6 // Protel DXP Scope 1 Expression Was: IsKeepOut and IsTrack
Clearance Clearance_Keepout [All] p0 off: scope1count=1 scope1_0_kind=Board scope1_0_value=Board scope2count=1 scope2_0_kind=Board scope2_0_value=Board commentlength=60 gap=20 // Protel DXP Scope 1 Expression Was: IsKeepOut and IsTrack
Clearance Clearance_LVDS_Track [All] p0 off: scope1count=1 scope1_0_kind=Board scope1_0_value=Board scope2count=1 scope2_0_kind=Board scope2_0_value=Board commentlength=69 gap=5 // Protel DXP Scope 2 Expression Was: istrack and InNetClass('LVDS')
Clearance Clearance_LVDS [All] p0 off: scope1count=1 scope1_0_kind=Board scope1_0_value=Board scope2count=1 scope2_0_kind=Board scope2_0_value=Board commentlength=108 gap=8 // Protel DXP Scope 2 Expression Was: (isvia or IsThruPin) and (not InNetClass('LVDS') or not InNet('GND'))
Clearance Clearance_Region [All] p0 off: scope1count=1 scope1_0_kind=Board scope1_0_value=Board scope2count=1 scope2_0_kind=Board scope2_0_value=Board commentlength=46 gap=5 // Protel DXP Scope 2 Expression Was: IsTrack
Clearance "Clr_L2_GND Cut out (400 Mircrons)" [All] p0 off: scope1count=1 scope1_0_kind=Board scope1_0_value=Board scope2count=1 scope2_0_kind=Board scope2_0_value=Board commentlength=48 gap=0 // Protel DXP Scope 2 Expression Was: IsKeepOut
Clearance "Clr_L1_GND Cut Out (800 Mirons)_1" [All] p0: scope1count=1 scope1_0_kind=Layer scope1_0_value=MID1 scope2count=1 scope2_0_kind=Board scope2_0_value=Board commentlength=0 gap=6
Clearance "Clearance_Diff Pairs_LVDS" [All] p0: scope1count=1 scope1_0_kind=NetClass scope1_0_value="Diff Pairs" scope2count=1 scope2_0_kind=NetClass scope2_0_value="Diff Pairs" commentlength=0 gap=6
Clearance "Clr_L1_GND Cut Out (800 Mirons)" [All] p0 off: scope1count=1 scope1_0_kind=Board scope1_0_value=Board scope2count=1 scope2_0_kind=Board scope2_0_value=Board commentlength=48 gap=0 // Protel DXP Scope 2 Expression Was: IsKeepOut
Clearance "Clearance_TX and RX" [All] p0: scope1count=1 scope1_0_kind=NetClass scope1_0_value="TX and RX" scope2count=1 scope2_0_kind=Board scope2_0_value=Board commentlength=0 gap=8
Clearance Clearance_BGA [All] p0 off: scope1count=1 scope1_0_kind=Board scope1_0_value=Board scope2count=1 scope2_0_kind=Board scope2_0_value=Board commentlength=57 gap=4 // Protel DXP Scope 1 Expression Was: WithinRoom('BGA1')
Clearance [All] p0: scope1count=1 scope1_0_kind=Board scope1_0_value=Board scope2count=1 scope2_0_kind=Board scope2_0_value=Board commentlength=0 gap=8
Clearance Clearance_Fid [All] p0 off: scope1count=1 scope1_0_kind=Board scope1_0_value=Board scope2count=1 scope2_0_kind=Board scope2_0_value=Board commentlength=81 gap=0 // Protel DXP Scope 2 Expression Was: IsPad and InComponentClass('FiducialMark')
Clearance Clearance_Fid [IsKeepOut and InComponentClass('FiducialMark') vs IsPad and InComponentClass('FiducialMark')] p1: gap=0 ignorepadtopadclearanceinfootprint=FALSE
Clearance Clearance_KO [IsKeepOut vs IsSMTPin] p2: gap=1 ignorepadtopadclearanceinfootprint=FALSE
Clearance "Clr_L2_GND Cut out (400 Mircrons)" [OnLayer('L2_GND') and InPolygon vs IsKeepOut] p3: gap=0 ignorepadtopadclearanceinfootprint=FALSE except(7: Arc-Arc Arc-Track)
Clearance "Clearance_TX and RX" [InNetClass('TX and RX')] p4: gap=8 ignorepadtopadclearanceinfootprint=FALSE except(0: Arc-Hole Track-Hole SMDPad-Hole THPad-Hole Via-Hole Fill-Hole Poly-Hole Region-Hole Text-Hole; 4: Arc-Text Track-Text SMDPad-Text THPad-Text Via-Text Fill-Text Poly-Text Region-Text Text-Text; 7.7: Fill-Fill Fill-Poly Fill-Region Poly-Poly Poly-Region Region-Region; 7.9: Arc-Via Track-Via; 10: Arc-SMDPad Arc-THPad Track-SMDPad Track-THPad SMDPad-SMDPad SMDPad-THPad SMDPad-Via THPad-THPad THPad-Via)
Clearance Clearance_KO-J5 [IsKeepOut and IsTrack vs InComponent('J5')] p5: gap=19.6 ignorepadtopadclearanceinfootprint=FALSE
Clearance Clearance_Keepout [IsKeepOut and IsTrack] p6: gap=20 ignorepadtopadclearanceinfootprint=FALSE
Clearance Clearance_LVDS_Track [istrack and InNetClass('LVDS') vs istrack and InNetClass('LVDS')] p7: gap=5 ignorepadtopadclearanceinfootprint=FALSE except(3.9: Arc-Arc Arc-Track Track-Track)
Clearance Clearance_LVDS [InNetClass('LVDS') and IsTrack vs (isvia or IsThruPin) and (not InNetClass('LVDS') or not InNet('GND'))] p8: gap=8 ignorepadtopadclearanceinfootprint=FALSE
Clearance Clearance_Region [isregion and incomponent('U4') vs IsTrack] p9: gap=5 ignorepadtopadclearanceinfootprint=FALSE
Clearance "Clr_L1_GND Cut Out (800 Mirons)_1" [OnLayer('L2_GND')] p10: gap=6 ignorepadtopadclearanceinfootprint=FALSE except(0: Arc-Hole Track-Hole SMDPad-Hole THPad-Hole Via-Hole Fill-Hole Poly-Hole Region-Hole Text-Hole; 8: Arc-Fill Arc-Poly Arc-Region Track-Fill Track-Poly Track-Region SMDPad-Fill SMDPad-Poly SMDPad-Region THPad-Fill THPad-Poly THPad-Region Via-Fill Via-Poly Via-Region Fill-Fill Fill-Poly Fill-Region Poly-Poly Poly-Region Region-Region)
Clearance "Clearance_Diff Pairs_LVDS" [InNetClass('Diff Pairs') vs InNetClass('Diff Pairs')] p11: gap=6 ignorepadtopadclearanceinfootprint=FALSE except(0: Arc-Hole Track-Hole SMDPad-Hole THPad-Hole Via-Hole Fill-Hole Poly-Hole Region-Hole Text-Hole; 3.9: Arc-Arc Arc-Track Track-Track; 4: Arc-SMDPad Arc-THPad Arc-Via Track-SMDPad Track-THPad Track-Via; 8: Arc-Fill Arc-Poly Arc-Region Track-Fill Track-Poly Track-Region Via-Fill Via-Poly Via-Region Fill-Fill Fill-Poly Fill-Region Poly-Poly Poly-Region Region-Region)
Clearance "Clr_L1_GND Cut Out (800 Mirons)" [OnTopLayer and InPoly vs IsKeepOut] p12: gap=0 ignorepadtopadclearanceinfootprint=FALSE
Clearance Clearance_BGA [WithinRoom('BGA1')] p13: gap=4 ignorepadtopadclearanceinfootprint=FALSE except(0: Arc-Hole Track-Hole SMDPad-Hole THPad-Hole Via-Hole Fill-Hole Poly-Hole Region-Hole Text-Hole; 1: Arc-SMDPad; 6: SMDPad-Poly THPad-Poly Via-Poly; 7.5: Region-Region; 7.87: Arc-Text Track-Text SMDPad-Text THPad-Text Via-Text Fill-Text Poly-Text Region-Text Text-Text; 8: Arc-Poly Track-THPad Track-Poly THPad-THPad Fill-Poly Poly-Poly)
Clearance [All] p14: gap=8 ignorepadtopadclearanceinfootprint=TRUE except(0: Arc-Hole Track-Hole SMDPad-Hole THPad-Hole Via-Hole Fill-Hole Poly-Hole Region-Hole Text-Hole; 5: Arc-Arc Arc-Track Arc-SMDPad Track-Track Track-SMDPad; 5.1: SMDPad-SMDPad; 6: Arc-THPad Arc-Via Arc-Text Track-THPad Track-Via Track-Text SMDPad-THPad SMDPad-Via SMDPad-Text THPad-THPad THPad-Via THPad-Text Via-Via Via-Text Fill-Text Poly-Text Region-Text Text-Text)
ComponentClearance ComponentClearance_MatingCon-3D [All] p0 off: scope1count=1 scope1_0_kind=Board scope1_0_value=Board scope2count=1 scope2_0_kind=Board scope2_0_value=Board commentlength=57 gap=0 collisioncheckmode=3 // Protel DXP Scope 2 Expression Was: not InAnyComponent
ComponentClearance "ComponentClearance_WEE Logo" [All] p0: scope1count=1 scope1_0_kind=Component scope1_0_value=Logo4 scope2count=1 scope2_0_kind=Board scope2_0_value=Board commentlength=0 gap=0 collisioncheckmode=3
ComponentClearance ComponentClearance_R77 [All] p0: scope1count=1 scope1_0_kind=Component scope1_0_value=R77 scope2count=1 scope2_0_kind=Component scope2_0_value=Logo1 commentlength=0 gap=0 collisioncheckmode=3
ComponentClearance ComponentClearance_Logo [All] p0: scope1count=1 scope1_0_kind=ComponentClass scope1_0_value=Logo scope2count=1 scope2_0_kind=Board scope2_0_value=Board commentlength=0 gap=0 collisioncheckmode=3
ComponentClearance "ComponentClearance_Mounting Holes_Fiducial Marks" [All] p0: scope1count=1 scope1_0_kind=ComponentClass scope1_0_value=FiducialMark scope2count=1 scope2_0_kind=PadClass scope2_0_value="Mounting Holes PADS" commentlength=0 gap=50 collisioncheckmode=3
ComponentClearance [All] p0: scope1count=1 scope1_0_kind=Board scope1_0_value=Board scope2count=1 scope2_0_kind=Board scope2_0_value=Board commentlength=0 gap=10 collisioncheckmode=3
ComponentClearance ComponentClearance_MatingCon-3D [All vs not InAnyComponent] p1: gap=0 collisioncheckmode=3 verticalgap=0 showdistances=FALSE
ComponentClearance "ComponentClearance_WEE Logo" [InComponent('Logo4')] p2: gap=0 collisioncheckmode=3 verticalgap=0 showdistances=TRUE
ComponentClearance ComponentClearance_R77 [InComponent('R77') vs InComponent('Logo1')] p3: gap=0 collisioncheckmode=3 verticalgap=0 showdistances=TRUE
ComponentClearance ComponentClearance_Logo [InComponentClass('Logo')] p4: gap=0 collisioncheckmode=3 verticalgap=0 showdistances=TRUE
ComponentClearance "ComponentClearance_Mounting Holes_Fiducial Marks" [InComponentClass('FiducialMark') vs InPadClass('Mounting Holes PADS')] p5: gap=50 collisioncheckmode=3 verticalgap=10 showdistances=TRUE
ComponentClearance [All] p6: gap=10 collisioncheckmode=3 verticalgap=10 showdistances=TRUE
DiffPairsRouting [All] p0: scope1count=1 scope1_0_kind=Board scope1_0_value=Board scope2count=1 scope2_0_kind=Board scope2_0_value=Board commentlength=0
DiffPairsRouting [All] p1: maxlimit=7.2 minlimit=5 mostfreqgap=7.2 toplayer_maxgap=5 toplayer_prefgap=5 toplayer_minwidth=4 toplayer_maxwidth=5.2 toplayer_prefwidth=5.2 midlayer1_mingap=7.2 midlayer1_minwidth=4.8 midlayer1_maxwidth=4.8 midlayer1_prefwidth=4.8 midlayer2_mingap=7.2 midlayer2_minwidth=4.8 midlayer2_maxwidth=4.8 midlayer2_prefwidth=4.8 midlayer3_mingap=7.2 midlayer3_minwidth=4.8 midlayer3_maxwidth=4.8 midlayer3_prefwidth=4.8 midlayer4_mingap=7.2 midlayer4_minwidth=4.8 midlayer4_maxwidth=4.8 midlayer4_prefwidth=4.8 midlayer5_mingap=7.2 midlayer5_minwidth=4.8 midlayer5_maxwidth=4.8 midlayer5_prefwidth=4.8 midlayer6_mingap=7.2 midlayer6_minwidth=4.8 midlayer6_maxwidth=4.8 midlayer6_prefwidth=4.8 bottomlayer_maxgap=5 bottomlayer_prefgap=5 bottomlayer_minwidth=5.2 bottomlayer_maxwidth=5.2 bottomlayer_prefwidth=5.2 maxuncoupledlength=500
FabricationTestPointUsage TestPointUsage [All] p0: scope1count=1 scope1_0_kind=Board scope1_0_value=Board scope2count=1 scope2_0_kind=Board scope2_0_value=Board commentlength=0 valid=2 allowmultiple=FALSE
FabricationTestPointUsage TestPointUsage [All] p1: valid=2 allowmultiple=FALSE
FabricationTestpoint Testpoint [All] p0: scope1count=1 scope1_0_kind=Board scope1_0_value=Board scope2count=1 scope2_0_kind=Board scope2_0_value=Board commentlength=0 side=3 testpointundercomponent=TRUE minsize=40 maxsize=100 preferedsize=60 minholesize=0 maxholesize=40 preferedholesize=32 testpointgrid=1
FabricationTestpoint Testpoint [All] p1: side=3 testpointundercomponent=TRUE minsize=40 maxsize=100 preferedsize=60 minholesize=0 maxholesize=40 preferedholesize=32 testpointgrid=1 allowsidetop=TRUE allowsidebottom=TRUE usegrid=TRUE gridtolerance=0.01
FanoutControl Fanout_LCC [All] p0 off: scope1count=1 scope1_0_kind=Board scope1_0_value=Board scope2count=1 scope2_0_kind=Board scope2_0_value=Board commentlength=69 // Protel DXP Scope 1 Expression Was: IsLCC   Fanout_LCC (Default Rule)
FanoutControl Fanout_BGA [All] p0 off: scope1count=1 scope1_0_kind=Board scope1_0_value=Board scope2count=1 scope2_0_kind=Board scope2_0_value=Board commentlength=69 // Protel DXP Scope 1 Expression Was: IsBGA   Fanout_BGA (Default Rule)
FanoutControl Fanout_SOIC [All] p0 off: scope1count=1 scope1_0_kind=Board scope1_0_value=Board scope2count=1 scope2_0_kind=Board scope2_0_value=Board commentlength=71 // Protel DXP Scope 1 Expression Was: IsSOIC   Fanout_SOIC (Default Rule)
FanoutControl Fanout_Default [All] p0: scope1count=1 scope1_0_kind=Board scope1_0_value=Board scope2count=1 scope2_0_kind=Board scope2_0_value=Board commentlength=30 // Fanout_Default (Default Rule)
FanoutControl Fanout_Small [All] p0 off: scope1count=1 scope1_0_kind=Board scope1_0_value=Board scope2count=1 scope2_0_kind=Board scope2_0_value=Board commentlength=84 // Protel DXP Scope 1 Expression Was: (CompPinCount < 5)   Fanout_Small (Default Rule)
FanoutControl Fanout_LCC [IsLCC] p1: bgadir=Out bgaviamode=Centered fanoutstyle=Auto fanoutdirection=Alternating viagrid=1 // Fanout_LCC (Default Rule)
FanoutControl Fanout_BGA [IsBGA] p2: bgadir=Out bgaviamode=Centered fanoutstyle=Auto fanoutdirection=Alternating viagrid=1 // Fanout_BGA (Default Rule)
FanoutControl Fanout_Default [All] p4: bgadir=Out bgaviamode=Centered fanoutstyle=Auto fanoutdirection=Alternating viagrid=1 // Fanout_Default (Default Rule)
FanoutControl Fanout_Small [(CompPinCount < 5)] p5: bgadir=Out bgaviamode=Centered fanoutstyle=Auto fanoutdirection=OutThenIn viagrid=1 // Fanout_Small (Default Rule)
Height Room_Hieght [All] p0 off: scope1count=1 scope1_0_kind=Board scope1_0_value=Board scope2count=1 scope2_0_kind=Board scope2_0_value=Board commentlength=69 // Protel DXP Scope 1 Expression Was: WithinRoom('Room_Hieght 1 MM')
Height Room_Hieght [WithinRoom('Room_Hieght 1 MM')] p1: minheight=0 maxheight=41.34 prefheight=39.37
HoleSize [All] p0: scope1count=1 scope1_0_kind=Board scope1_0_value=Board scope2count=1 scope2_0_kind=Board scope2_0_value=Board commentlength=0 absolutevalues=TRUE maxlimit=280 minlimit=5.9 maxpercent=80.000 minpercent=20.000
HoleSize [All] p1: absolutevalues=TRUE maxlimit=280 minlimit=5.9 maxpercent=80.000 minpercent=20.000
HoleToHoleClearance HoleToHoleClearance_1 [All] p0 off: scope1count=1 scope1_0_kind=Board scope1_0_value=Board scope2count=1 scope2_0_kind=Board scope2_0_value=Board commentlength=77 // Protel DXP Scope 2 Expression Was: InDrillLayerPair('Top Layer - L2_GND')
HoleToHoleClearance [All] p0: scope1count=1 scope1_0_kind=Board scope1_0_value=Board scope2count=1 scope2_0_kind=Board scope2_0_value=Board commentlength=0
HoleToHoleClearance HoleToHoleClearance_1 [InDrillLayerPair('Top Layer - L2_GND') vs InDrillLayerPair('Top Layer - L2_GND')] p1: gap=7.7 allowstackedmicrovias=TRUE
HoleToHoleClearance [All] p2: gap=8 allowstackedmicrovias=TRUE
LayerPairs [All] p0: scope1count=1 scope1_0_kind=Board scope1_0_value=Board scope2count=1 scope2_0_kind=Board scope2_0_value=Board commentlength=0 enforce=TRUE
MatchedLengths MatchedLengths_SPI [All] p0 off: scope1count=1 scope1_0_kind=Board scope1_0_value=Board scope2count=1 scope2_0_kind=Board scope2_0_value=Board commentlength=60 tolerance=2 amplitude=200 gap=20 style=90-Degree // Protel DXP Scope 1 Expression Was: InxSignalClass('SPI')
MatchedLengths MatchedLengths-J2-J6 [All] p0 off: scope1count=1 scope1_0_kind=Board scope1_0_value=Board scope2count=1 scope2_0_kind=Board scope2_0_value=Board commentlength=62 tolerance=15 amplitude=200 gap=20 style=90-Degree // Protel DXP Scope 1 Expression Was: InxSignalClass('J2-J6')
MatchedLengths MatchedLengths_U1-J6 [All] p0 off: scope1count=1 scope1_0_kind=Board scope1_0_value=Board scope2count=1 scope2_0_kind=Board scope2_0_value=Board commentlength=62 tolerance=15 amplitude=200 gap=20 style=90-Degree // Protel DXP Scope 1 Expression Was: InxSignalClass('U1-J6')
MatchedLengths MatchedLengths-U1-J1 [All] p0 off: scope1count=1 scope1_0_kind=Board scope1_0_value=Board scope2count=1 scope2_0_kind=Board scope2_0_value=Board commentlength=62 tolerance=15 amplitude=200 gap=20 style=90-Degree // Protel DXP Scope 1 Expression Was: InxSignalClass('U1-J1')
MatchedLengths MatchedLengths_Pairs [All] p0 off: scope1count=1 scope1_0_kind=Board scope1_0_value=Board scope2count=1 scope2_0_kind=Board scope2_0_value=Board commentlength=69 tolerance=10 amplitude=200 gap=20 style=90-Degree // Protel DXP Scope 1 Expression Was: InxSignalClass('All xSignals')
MatchedLengths MatchedLengths_SPI [InxSignalClass('SPI')] p1: tolerance=2 checknetsindiffpair=FALSE checkdiffpairvsdiffpair=TRUE checkxsignals=TRUE checkothers=TRUE
MatchedLengths MatchedLengths-J2-J6 [InxSignalClass('J2-J6')] p2: tolerance=15 checknetsindiffpair=FALSE checkdiffpairvsdiffpair=TRUE checkxsignals=TRUE checkothers=TRUE
MatchedLengths MatchedLengths_U1-J6 [InxSignalClass('U1-J6')] p3: tolerance=15 checknetsindiffpair=FALSE checkdiffpairvsdiffpair=TRUE checkxsignals=TRUE checkothers=TRUE
MatchedLengths MatchedLengths-U1-J1 [InxSignalClass('U1-J1')] p4: tolerance=15 checknetsindiffpair=FALSE checkdiffpairvsdiffpair=TRUE checkxsignals=TRUE checkothers=TRUE
MatchedLengths MatchedLengths_Pairs [InxSignalClass('All xSignals')] p5: tolerance=10 checknetsindiffpair=TRUE checkdiffpairvsdiffpair=FALSE checkxsignals=FALSE checkothers=FALSE
MinimumAnnularRing MinimumAnnularRing_ThermalPadVias [All] p0 off: scope1count=1 scope1_0_kind=Board scope1_0_value=Board scope2count=1 scope2_0_kind=Board scope2_0_value=Board commentlength=63 minimumring=3.9 // Protel DXP Scope 1 Expression Was: IsVia and InAnyComponent
MinimumAnnularRing [All] p0: scope1count=1 scope1_0_kind=Board scope1_0_value=Board scope2count=1 scope2_0_kind=Board scope2_0_value=Board commentlength=0 minimumring=3.9
MinimumAnnularRing MinimumAnnularRing_ThermalPadVias [IsVia and InAnyComponent] p1: minimumring=3.9
MinimumAnnularRing [All] p2: minimumring=3.9
MinimumSolderMaskSliver MinimumSolderMaskSliver_Logo [All] p0: scope1count=1 scope1_0_kind=ComponentClass scope1_0_value=Logo scope2count=1 scope2_0_kind=ComponentClass scope2_0_value=Logo commentlength=0
MinimumSolderMaskSliver [All] p0: scope1count=1 scope1_0_kind=Board scope1_0_value=Board scope2count=1 scope2_0_kind=Board scope2_0_value=Board commentlength=0
MinimumSolderMaskSliver MinimumSolderMaskSliver_Logo [InComponentClass('Logo') vs InComponentClass('Logo')] p1: minsoldermaskwidth=0.7
MinimumSolderMaskSliver [All] p2: minsoldermaskwidth=3.5
NetAntennae [All] p0: scope1count=1 scope1_0_kind=Board scope1_0_value=Board scope2count=1 scope2_0_kind=Board scope2_0_value=Board commentlength=0
PasteMaskExpansion [All] p0: scope1count=1 scope1_0_kind=Board scope1_0_value=Board scope2count=1 scope2_0_kind=Board scope2_0_value=Board commentlength=0 expansion=0
PlaneClearance [All] p0: scope1count=1 scope1_0_kind=Board scope1_0_value=Board scope2count=1 scope2_0_kind=Board scope2_0_value=Board commentlength=0 clearance=20
PlaneConnect [All] p0: scope1count=1 scope1_0_kind=Board scope1_0_value=Board scope2count=1 scope2_0_kind=Board scope2_0_value=Board commentlength=0 planeconnectstyle=Relief reliefexpansion=10 reliefentries=4 reliefconductorwidth=10 reliefairgap=10
PlaneConnect [All] p1: planeconnectstyle=Relief reliefexpansion=10 reliefentries=4 reliefconductorwidth=10 reliefairgap=10
PolygonConnect [All] p0: scope1count=1 scope1_0_kind=Board scope1_0_value=Board scope2count=1 scope2_0_kind=Board scope2_0_value=Board commentlength=0 connectstyle=Direct reliefconductorwidth=10 reliefentries=4 polygonreliefangle="90 Angle"
PolygonConnect [All] p1: connectstyle=Direct reliefconductorwidth=10 reliefentries=4 polygonreliefangle="90 Angle" airgapwidth=10
RoomDefinition BGA1 [All] p0 off: scope1count=1 scope1_0_kind=Board scope1_0_value=Board scope2count=1 scope2_0_kind=Board scope2_0_value=Board commentlength=57 region_x1=23660000 region_y1=31370000 region_x2=36912838 region_y2=46780017 confinementstyle=ConfineIn // Protel DXP Scope 1 Expression Was: WithinRoom('BGA1')
RoomDefinition BGA1 [WithinRoom('BGA1')] p1: confinementstyle=ConfineIn formatcopy=TRUE lockcomponents=FALSE outline 830,2365.43 1999.28,2365.43 1999.28,1605.71 1921,1527.43 1921,1493.43 1663,1235.43 1415,1235.43 1414,1234.43 1414,1061.43 1477,998.43 1477,914.43 1467,904.43 1435,904.43 1418,887.43 1362,887.43 1362,841.43 1345,824.43 1266,824.43 1256,834.43 1256,868.43 1224,900.43 1190,900.43 1177,913.43 1177,954.43 1084,1047.43 904,1047.43 839,1112.43 839,1258.43 807,1290.43 729,1290.43 711,1272.43 681,1272.43 674,1279.43 674,1372.43 678,1376.43 808,1376.43 844,1412.43 844,1609.43 830,1623.43
RoutingCorners [All] p0: scope1count=1 scope1_0_kind=Board scope1_0_value=Board scope2count=1 scope2_0_kind=Board scope2_0_value=Board commentlength=0 cornerstyle=45-Degree minsetback=100 maxsetback=100
RoutingLayers [All] p0: scope1count=1 scope1_0_kind=Board scope1_0_value=Board scope2count=1 scope2_0_kind=Board scope2_0_value=Board commentlength=0 top layer=Automatic mid layer 1=Automatic mid layer 2=Automatic mid layer 3=Automatic mid layer 4=Automatic mid layer 5=Automatic mid layer 6=Automatic bottom layer=Automatic
RoutingPriority [All] p0: scope1count=1 scope1_0_kind=Board scope1_0_value=Board scope2count=1 scope2_0_kind=Board scope2_0_value=Board commentlength=0
RoutingTopology [All] p0: scope1count=1 scope1_0_kind=Board scope1_0_value=Board scope2count=1 scope2_0_kind=Board scope2_0_value=Board commentlength=0 topology=Shortest
RoutingVias ThermalPadVias [All] p0 off: scope1count=1 scope1_0_kind=Board scope1_0_value=Board scope2count=1 scope2_0_kind=Board scope2_0_value=Board commentlength=63 holewidth=7.87 width=19.68 viastyle="Through Hole" minholewidth=5 minwidth=13 maxholewidth=12.99 maxwidth=23.62 // Protel DXP Scope 1 Expression Was: IsVia and InAnyComponent
RoutingVias [All] p0: scope1count=1 scope1_0_kind=Board scope1_0_value=Board scope2count=1 scope2_0_kind=Board scope2_0_value=Board commentlength=0 holewidth=12.2 width=22.4 viastyle="Through Hole" minholewidth=5.9 minwidth=14 maxholewidth=20 maxwidth=40
RoutingVias ThermalPadVias [IsVia and InAnyComponent] p1: holewidth=7.87 width=19.68 viastyle="Through Hole" minholewidth=5 minwidth=13 maxholewidth=12.99 maxwidth=23.62
RoutingVias [All] p2: holewidth=12.2 width=22.4 viastyle="Through Hole" minholewidth=5.9 minwidth=14 maxholewidth=20 maxwidth=40
SMDToCorner [All] p0: scope1count=1 scope1_0_kind=Board scope1_0_value=Board scope2count=1 scope2_0_kind=Board scope2_0_value=Board commentlength=0 distance=25000
SMDToCorner [All] p1: distance=25000
ShortCircuit [All] p0: scope1count=1 scope1_0_kind=Board scope1_0_value=Board scope2count=1 scope2_0_kind=Board scope2_0_value=Board commentlength=0 allowed=FALSE
SilkToBoardRegionClearance [All] p0 off: scope1count=1 scope1_0_kind=Board scope1_0_value=Board scope2count=1 scope2_0_kind=Board scope2_0_value=Board commentlength=130 // Protel DXP Scope 1 Expression Was: Not ((IsComment or IsDesignator) And (Hide <> 'False')) and not InRegion(1000,500,4000,800)
SilkToBoardRegionClearance [Not ((IsComment or IsDesignator) And (Hide <> 'False')) and not InRegion(1000,500,4000,800)] p1:
SilkToSilkClearance [All] p0: scope1count=1 scope1_0_kind=Board scope1_0_value=Board scope2count=1 scope2_0_kind=Board scope2_0_value=Board commentlength=0
SilkToSilkClearance [All] p1: silktosilkclearance=3
SilkToSolderMaskClearance SilkToSolderMaskClearance_OutLine [All] p0 off: scope1count=1 scope1_0_kind=Board scope1_0_value=Board scope2count=1 scope2_0_kind=Board scope2_0_value=Board commentlength=65 // Protel DXP Scope 1 Expression Was: istrack and InAnyComponent
SilkToSolderMaskClearance SilkscreenOverComponentPads [All] p0 off: scope1count=1 scope1_0_kind=Board scope1_0_value=Board scope2count=1 scope2_0_kind=Board scope2_0_value=Board commentlength=44 // Protel DXP Scope 1 Expression Was: IsPad
SilkToSolderMaskClearance SilkToSolderMaskClearance_OutLine [istrack and InAnyComponent] p1: minsilkscreentomaskgap=0 clearancetoexposedcopper=FALSE
SilkToSolderMaskClearance SilkscreenOverComponentPads [IsPad] p2: minsilkscreentomaskgap=3 clearancetoexposedcopper=FALSE
SolderMaskExpansion [All] p0: scope1count=1 scope1_0_kind=Board scope1_0_value=Board scope2count=1 scope2_0_kind=Board scope2_0_value=Board commentlength=0 expansion=0
SolderMaskExpansion [All] p1: expansion=0
UnRoutedNet [All] p0: scope1count=1 scope1_0_kind=Board scope1_0_value=Board scope2count=1 scope2_0_kind=Board scope2_0_value=Board commentlength=0
UnpouredPolygon [All] p0: scope1count=1 scope1_0_kind=Board scope1_0_value=Board scope2count=1 scope2_0_kind=Board scope2_0_value=Board commentlength=0
Width [All] p0: scope1count=1 scope1_0_kind=Board scope1_0_value=Board scope2count=1 scope2_0_kind=Board scope2_0_value=Board commentlength=0 maxlimit=100 minlimit=4 preferedwidth=6
Width [All] p1: maxlimit=100 minlimit=4 preferedwidth=6
13 further rules are at their usual default settings.

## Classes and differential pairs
net class Regions: 5V_IN 5V_IN_SW 5V_IN_USB GND NetD1_2 NetD2_2 SW2_CAP
net class 0.5A: RADAR_3V3 VCC_LD_SW_3V3
net class 0.85A: CB_PMIC_1V8 PMIC_1V8 RADAR_1V8 SW3
net class 2.5A: 5V_IN 5V_IN_SW 5V_IN_USB CB_PMIC_1V0 NetD1_2 NetD2_2 PMIC_1V0 RADAR_1P0_RF1 RADAR_1P0_RF2 RADAR_VOUT_PA SW2 USB_5V
net class LVDS: NetJ1_28 NetJ1_30 NetJ1_34 NetJ1_36 NetJ1_40 NetJ1_42 NetJ1_46 NetJ1_48 NetJ2_21 NetJ2_23 NetJ2_27 NetJ2_29 NetJ2_39 NetJ2_41 NetJ6_20 NetJ6_22 NetJ6_26 NetJ6_28 NetJ6_32 NetJ6_34 NetJ6_38 NetJ6_40 NetJ6_44 NetJ6_46 NetJ6_50 NetJ6_52 NetJ6_56 NetJ6_58 RADAR_LVDS_0M RADAR_LVDS_0P RADAR_LVDS_1M RADAR_LVDS_1P RADAR_LVDS_2M RADAR_LVDS_2P RADAR_LVDS_3M RADAR_LVDS_3P RADAR_LVDS_CLKM RADAR_LVDS_CLKP RADAR_LVDS_FRCLKM RADAR_LVDS_FRCLKP RADAR_LVDS_VALIDM RADAR_LVDS_VALIDP
net class 1A: CB_PMIC_1V2 PMIC_1V2 RADAR_1V2 SW1
pad class "Mounting Holes PADS": Free-TH9
net class "Diff Pairs": NetJ1_28 NetJ1_30 NetJ1_34 NetJ1_36 NetJ1_40 NetJ1_42 NetJ1_46 NetJ1_48 RADAR_LVDS_0M RADAR_LVDS_0P RADAR_LVDS_1M RADAR_LVDS_1P RADAR_LVDS_CLKM RADAR_LVDS_CLKP RADAR_LVDS_FRCLKM RADAR_LVDS_FRCLKP
component class Logo: Logo1 Logo5
component class FiducialMark: FID1 FID2 FID3 FID4 FID5 FID6
component class Label: LBL1
component class PROC073D_Decoupling_caps: C1 C2 C3 C4 C5 C6 C7 C8 C9 C10 C11 C12 C13 C14 C15 C16 C17 C18 C19 C20 C21 C22 C23 C24 C25 C26 C27 C28 C29 C30 C64 C76 C77 C78 C79 C80 C81 C82 C83 C88 C89 C100 C101 C102 C103 C104 L1 L2 L3 L7 R1
component class PROC073D_EVM_Hardware: "CAUTION HOT SURFACE1" FID1 FID2 FID3 FID4 FID5 FID6 LBL1 Logo1 Logo2 LOGO3 Logo4 Logo5 ZZ1 ZZ2 ZZ3 ZZ4 ZZ5
component class PROC073D_HD_Connector_60Pin: J1 J2 R4 R5 R6 R7 R8 R9 R10 R11 R12 R13 R15 R16 R17 R18 R19 R20 R21 R22 R23 R24 R26 R27 R28 R30 R31 R32 R33 R34 R35 R36 R37 R38 R39 R40 R41 R42 R52 R53 R58 R59 R60 R61 R62 R63 R64 R65 R66 R67 R124 R125 R126 R127 R128 R129 R130 R131 R132 R133 R134 R135 R136 R137 R140 TP14
component class PROC073D_IWR6843_Chip: C31 C32 C33 R72 R73 R74 R75 R76 R77 R150 R152 R153 R154 R155 R156 R169 TP2 TP3 TP4 TP5 TP6 TP7 U1 Y1
component class PROC073D_Can_Interface: C37 C38 C39 C40 C41 C42 C43 J3 J4 R3 R68 R69 R70 R71 R78 R79 R80 R81 R82 R83 R84 R85 R86 R87 R88 R89 R216 U5 U12 U13
component class PROC073D_QSPI_Flash_section: C34 C35 R43 R44 R45 R46 R47 R48 R49 R50 R51 U2
component class PROC073D_Temp_Current_sensor: C36 C57 C58 C59 C63 C65 R2 R14 R25 R29 R54 R55 R56 R57 R94 R101 R103 R104 R105 R106 R107 R108 R109 R110 R111 R112 R113 R114 R115 R116 R117 R139 R142 R143 R144 R145 R146 R147 R151 R157 R158 R159 R160 R161 R162 U3 U6 U7 U8 U10 U11
net class "TX and RX": RX1 RX2 RX3 RX4 TX1 TX2 TX3
component class AssemblyNote: ZZ1 ZZ2 ZZ3 ZZ4 ZZ5
net class Flash: RADAR_QSPI_CS RADAR_QSPI_D0 RADAR_QSPI_D1 RADAR_QSPI_D2 RADAR_QSPI_D3 RADAR_QSPI_SCLK
component class PROC073D_Flash_USB_To_UART: C44 C45 C46 C47 C48 C49 C50 C51 C84 C85 C86 D1 D2 D4 FL1 FL2 J5 L9 L10 LD1 R90 R91 R92 R93 R95 R96 R97 R98 R99 R100 R102 R118 R119 R120 R121 TP1 TP8 U14 U15 U16
component class PROC073D_HD_DCA_Conn: C52 C53 C92 C93 C94 C95 C96 C97 D5 D7 J6 LD2 LD4 Q1 R122 R123 R138 R141 R148 R149 R163 R164 R165 R166 R167 R168 R170 R171 R212 R213 R214 R215 R217 R218 R219 R220 R221 R222 R223 R224 R225 R226 R227 R228 R229 R230 S2 S3 SW1 SW2 TP12 TP13 U17
component class PROC073D_PMIC: C54 C55 C56 C60 C61 C62 C66 C67 C68 C69 C70 C71 C72 C73 C74 C75 C87 C90 C91 C98 C99 Case D3 D6 FL3 FL4 L4 L5 L6 L8 L11 L12 LD3 Q2 R172 R173 R174 R175 R176 R177 R178 R179 R180 R181 R182 R183 R184 R185 R186 R187 R188 R189 R190 R191 R192 R193 R194 R195 R196 R197 R198 R199 R200 R201 TP9 TP10 TP11 U4 U9
component class PROC073D_SOP_Ctrl: R202 R203 R204 R205 R206 R207 R208 R209 R210 R211 S1
differential pair NewDifferentialPair21: +NetJ6_38 -NetJ6_40
differential pair NewDifferentialPair20: +RADAR_LVDS_2P -RADAR_LVDS_2M
differential pair NewDifferentialPair19: +NetJ2_23 -NetJ2_21
differential pair NewDifferentialPair18: +NetJ6_32 -NetJ6_34
differential pair NewDifferentialPair17: +RADAR_LVDS_3P -RADAR_LVDS_3M
differential pair NewDifferentialPair16: +NetJ2_29 -NetJ2_27
differential pair NewDifferentialPair15: +NetJ2_41 -NetJ2_39
differential pair NewDifferentialPair14: +RADAR_LVDS_VALIDP -RADAR_LVDS_VALIDM
differential pair NewDifferentialPair13: +NetJ6_20 -NetJ6_22
differential pair NewDifferentialPair12: +NetJ6_28 -NetJ6_26
differential pair NewDifferentialPair11: +NetJ6_44 -NetJ6_46
differential pair NewDifferentialPair10: +NetJ6_52 -NetJ6_50
differential pair NewDifferentialPair9: +NetJ6_58 -NetJ6_56
differential pair NewDifferentialPair8: +NetJ1_30 -NetJ1_28
differential pair NewDifferentialPair7: +NetJ1_36 -NetJ1_34
differential pair NewDifferentialPair6: +NetJ1_42 -NetJ1_40
differential pair NewDifferentialPair5: +NetJ1_48 -NetJ1_46
differential pair NewDifferentialPair4: +RADAR_LVDS_FRCLKM -RADAR_LVDS_FRCLKP
differential pair NewDifferentialPair3: +RADAR_LVDS_CLKM -RADAR_LVDS_CLKP
differential pair NewDifferentialPair2: +RADAR_LVDS_1M -RADAR_LVDS_1P
differential pair " ": +RADAR_LVDS_0M -RADAR_LVDS_0P

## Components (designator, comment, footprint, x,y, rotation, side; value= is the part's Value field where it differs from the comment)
C1 "CGA5L1X7R0J226M160AC" 1206_180 1230.15,775.38 r180 bottom
C2 "CGA5L1X7R0J226M160AC" 1206_180 1021.11,2061.53 r270 bottom
C3 "CGA5L1X7R0J226M160AC" 1206_180 882.8,1740.98 r90 bottom
C4 "GCM155R71C224KE02D" 0402L 1374.59,1473.43 r270 top
C5 "GCM155R71C224KE02D" 0402L 1419.18,1147.84 r180 top
C6 "CGA2B3X7R1H473K050BB" 0402L 1325,1206.43 r0 bottom
C7 "C0805C106M8RACTU" 0805_HV 1542.32,1662.55 r180 bottom
C8 "C0805C106M8RACTU" 0805_HV 1542.32,1752.76 r180 bottom
C9 "GCM155R71C224KE02D" 0402L 1200,1061.43 r90 bottom
C10 "GCM155R71C224KE02D" 0402L 960.59,1266.43 r180 bottom
C11 "GCM155R71C224KE02D" 0402L 991.8,1460.26 r270 bottom
C12 "GCM155R71C224KE02D" 0402L 1190.24,1421.11 r180 bottom
C13 "C0805C106M8RACTU" 0805_HV 1186.86,1481.66 r180 bottom
C14 "GCM155R71C224KE02D" 0402L 1505.59,1146.43 r180 top
C15 "C0805C106M8RACTU" 0805_HV 1615,1141.43 r270 top
C16 "GCM155R71C224KE02D" 0402L 1163.59,916.43 r90 top
C17 "GCM188R70J225KE22D" 0603 800.59,1276.43 r0 top
C18 "GCM188R71C105KA64D" 0603 1436.78,1072.84 r180 top
C19 "GCM155R71C224KE02D" 0402L 1025.8,1460.26 r270 bottom
C20 "GCM155R71C224KE02D" 0402L 1359.36,1547.4 r180 bottom
C21 "GCM155R71C224KE02D" 0402L 806.59,1227.43 r0 top
C22 "GCM188R71C105KA64D" 0603 1440.59,1216.43 r180 top
C23 "C0805C106M8RACTU" 0805_HV 999.85,1577.78 r90 bottom
C24 "C0805C106M8RACTU" 0805_HV 1357.15,1464.94 r180 bottom
C25 "GCM155R71C104KA55D" 0402L 875.59,1006.43 r0 top
C26 "GCM155R71C104KA55D" 0402L 1134.5,992.43 r90 top
C27 "GCM188R70J225KE22D" 0603 810.59,1056.43 r0 top
C28 "GCM155R71C224KE02D" 0402L 850.59,1361.43 r0 top
C29 "GCM155R71C224KE02D" 0402L 980.59,1206.43 r270 bottom
C30 "GCM155R71E103KA37D" 0402L 1103,1016.43 r270 bottom
C31 "GRM033C71A104KE14D" 0201 1049.59,1113.43 r90 bottom
C32 "GJM1555C1H4R7BB01D" 0402L 1435.59,966.43 r90 top
C33 "GJM1555C1H4R7BB01D" 0402L 1315.59,871.43 r180 top
C34 "CGA2B3X7R1H104K050BB" 0402L 635.7,618.33 r180 top
C35 "GCM188R71C105KA64D" 0603 647.51,552.29 r180 top
C36 "CGA2B3X7R1H104K050BB" 0402L 900,646.43 r90 bottom
C37 "C0402C104K8RACTU" 0402L 369.48,341.37 r90 bottom
C38 "C0402C104K8RACTU" 0402L 223.71,428.27 r270 bottom
C39 "GCM155R71H472KA37D" 0402L 243.19,263.8 r180 bottom
C40 "C0402C104K8RACTU" 0402L 238.73,135.39 r90 bottom
C41 "C0402C104K8RACTU" 0402L 211.15,205.08 r180 bottom
C42 "GCM155R71H472KA37D" 0402L 100.49,119.38 r0 bottom
C43 "C0402C104K8RACTU" 0402 682.22,418.42 r90 top
C44 "GRM033R6YA104KE14D" "FP-GRM033R6YA104KE14D_0201 (0603 Metric)-IPC_C" 1886.12,-6.42 r180 top
C45 "GRM033R6YA104KE14D" "FP-GRM033R6YA104KE14D_0201 (0603 Metric)-IPC_C" 1886.12,19.89 r180 top
C46 "CL05A106MP5NUNC" 0402_070 1790.76,-217.04 r270 top
C47 "CL05A106MP5NUNC" 0402_070 1829.82,-217.04 r90 top
C48 "GRM033R6YA104KE14D" "FP-GRM033R6YA104KE14D_0201 (0603 Metric)-IPC_C" 1892.6,234.77 r270 top
C49 "GRM033R6YA104KE14D" "FP-GRM033R6YA104KE14D_0201 (0603 Metric)-IPC_C" 1630.48,144.92 r180 top
C50 "GRM033R6YA104KE14D" "FP-GRM033R6YA104KE14D_0201 (0603 Metric)-IPC_C" 1605.7,313.9 r180 top
C51 "CL03A105MO3NRNH" FP-CL03A105MO3NRNH_0201-IPC_C 1710.29,234.43 r270 top
C52 "GRM033R6YA104KE14D" "FP-GRM033R6YA104KE14D_0201 (0603 Metric)-IPC_C" 639.02,1042.72 r0 top
C53 "GRM033R6YA104KE14D" "FP-GRM033R6YA104KE14D_0201 (0603 Metric)-IPC_C" 571.56,999.1 r0 top
C54 "TMK063CG391JT-F" "FP-TMK063CG391JT-F_0201 (0603 Metric)-IPC_C" 816.81,178.5 r180 top
C55 "TMK063CG391JT-F" "FP-TMK063CG391JT-F_0201 (0603 Metric)-IPC_C" 1221.31,125 r0 top
C56 "TMK063CG391JT-F" "FP-TMK063CG391JT-F_0201 (0603 Metric)-IPC_C" 821.11,435.45 r180 top
C57 "CGA2B3X7R1H104K050BB" 0402L 1221.73,322.88 r0 top
C58 "CGA2B3X7R1H104K050BB" 0402L 545.37,1700.76 r0 bottom
C59 "CGA2B3X7R1H104K050BB" 0402L 810.31,631.74 r0 bottom
C60 "TMK063CG391JT-F" "FP-TMK063CG391JT-F_0201 (0603 Metric)-IPC_C" 1158.44,442.7 r0 top
C61 "CL05A226MQ5N6J8" "FP-CL05A226MQ5N6J8_0402 (1005 Metric)-IPC_C" 986.51,105.67 r90 top
C62 "CL05A226MQ5N6J8" "FP-CL05A226MQ5N6J8_0402 (1005 Metric)-IPC_C" 1016.73,105.67 r90 top
C63 "CGA2B3X7R1H104K050BB" 0402L 898.74,1109.62 r180 bottom
C64 "CGA5L1X7R0J226M160AC" 1206_180 509.74,1895.02 r0 bottom
C65 "CGA2B3X7R1H104K050BB" 0402L 475,2126.43 r0 bottom
C66 "CL05A226MQ5N6J8" "FP-CL05A226MQ5N6J8_0402 (1005 Metric)-IPC_C" 983.92,559.16 r270 top
C67 "CL05A226MQ5N6J8" "FP-CL05A226MQ5N6J8_0402 (1005 Metric)-IPC_C" 1015.86,559.16 r270 top
C68 "LMK063BJ224MP-F" 0201_033L 1112.94,326.14 r270 top
C69 "CL10B105KQ8NNNC" 0603 760.98,719.45 r270 top
C70 "C0603C104J5RACTU" 0603 708.74,1036.43 r90 top
C71 "CGA2B3X7S2A102K050BB" 0402 933.74,916.43 r270 top
C72 "CL05A106MP5NUNC" 0402_070 1031.96,452.29 r180 top
C73 "CL05A106MP5NUNC" 0402_070 1031.68,202.29 r180 top
C74 "CL05A106MP5NUNC" 0402_070 969.08,452.29 r0 top
C75 "CL05A106MP5NUNC" 0402_070 969.08,202.29 r0 top
C76 "GCM32ER71C226KE19L" 1210_280 1417.84,1866.1 r0 bottom
C77 "GCM21BR71A106KE22L" 0805_HV 1392.88,1975.36 r0 bottom
C78 "GCM32ER71C226KE19L" 1210_280 1138.04,1849.51 r90 bottom
C79 "GCM21BR71A106KE22L" 0805_HV 1029.97,1824.55 r90 bottom
C80 "GCM32ER71C226KE19L" 1210_280 799.39,1586.85 r0 bottom
C81 "GCM21BR71A106KE22L" 0805_HV 730.68,1895.09 r0 bottom
C82 "GCM32ER71C226KE19L" 1210_280 1118.27,527.14 r0 bottom
C83 "GCM21BR71A106KE22L" 0805_HV 1103.01,650.54 r0 bottom
C84 "GCM155C71A474KE36D" 0402L 1751.34,191.02 r0 top
C85 "LMK105B7224KVHF" 0402S 1751.55,154.66 r0 top
C86 "GRT188R61A106KE13D" 0603S 1873.14,-164.46 r0 top
C87 "GRT188R61A106KE13D" 0603S 632.15,961.78 r0 top
C88 "GRT188R61A106KE13D" 0603S 1062.17,967.51 r270 bottom
C89 "LMK105B7224KVHF" 0402S 1136.85,982.08 r90 bottom
C90 "CL05A226MQ5N6J8" "FP-CL05A226MQ5N6J8_0402 (1005 Metric)-IPC_C" 956.3,105.67 r90 top
C91 "CL05A226MQ5N6J8" "FP-CL05A226MQ5N6J8_0402 (1005 Metric)-IPC_C" 1048.94,105.67 r90 top
C92 "GCM155C71A474KE36D" 0402L 1590.29,428.95 r180 top
C93 "GRT155C81A105KE01D" 0402L 1590.29,395.27 r180 top
C94 "LMK105B7224KVHF" 0402S 1590.29,361.6 r180 top
C95 "GRT188R61A106KE13D" 0603S 1716.14,445.98 r270 top
C96 "GRT188R61A106KE13D" 0603S 1763.58,445.98 r270 top
C97 "GRT188R61A106KE13D" 0603S 1668.5,445.98 r270 top
C98 "CL05A226MQ5N6J8" "FP-CL05A226MQ5N6J8_0402 (1005 Metric)-IPC_C" 954.18,559.16 r270 top
C99 "CL05A226MQ5N6J8" "FP-CL05A226MQ5N6J8_0402 (1005 Metric)-IPC_C" 1045.65,559.16 r270 top
C100 "CL05A226MQ5N6J8" "FP-CL05A226MQ5N6J8_0402 (1005 Metric)-IPC_C" 1153.91,1349.86 r270 bottom
C101 "CL05A226MQ5N6J8" "FP-CL05A226MQ5N6J8_0402 (1005 Metric)-IPC_C" 1087.5,1364.49 r270 bottom
C102 "CL05A226MQ5N6J8" "FP-CL05A226MQ5N6J8_0402 (1005 Metric)-IPC_C" 1414.23,1432.41 r270 top
C103 "CL05A226MQ5N6J8" "FP-CL05A226MQ5N6J8_0402 (1005 Metric)-IPC_C" 1306.03,1552.77 r90 top
C104 "CL05A226MQ5N6J8" "FP-CL05A226MQ5N6J8_0402 (1005 Metric)-IPC_C" 1352.23,1536.08 r0 top
"CAUTION HOT SURFACE1" "CAUTION HOT SURFACE" IEC_HotSurface_Small 579.8,2104.07 r0 top
D1 "NSR20F30NXT5G" DSN2_0603 1931.61,-260.55 r0 top
D2 "NSR20F30NXT5G" DSN2_0603 1778.12,296.35 r90 top
D3 "TLMY1000-GS08" TLMx1000_Yellow 657.08,104.57 r180 top
D4 "APHHS1005CGCK" APHHS1005_Green 1604.25,-62.83 r270 top
D5 "APHHS1005CGCK" APHHS1005_Green 345.96,1112.54 r90 top
D6 "APHHS1005CGCK" APHHS1005_Green 1273.45,175.99 r180 top
D7 "APHHS1005CGCK" APHHS1005_Green 1684.74,1093 r90 top
FID1 "Fiducial" Fiducial10-20 294.16,2105.3 r90 top
FID2 "Fiducial" Fiducial10-20 2091.36,170.94 r90 bottom
FID3 "Fiducial" Fiducial10-20 314.16,71.44 r90 bottom
FID4 "Fiducial" Fiducial10-20 613.28,-116.48 r90 top
FID5 "Fiducial" Fiducial10-20 294.16,2102.8 r90 bottom
FID6 "Fiducial" Fiducial10-20 2091.36,170.94 r90 top
J1 "QSH-030-01-L-D-A" Samtec_QSH-030-01-X-D-A 1708.74,801.43 r0 bottom locked
J2 "QSH-030-01-L-D-A" Samtec_QSH-030-01-X-D-A 417.24,801.43 r0 bottom locked
J3 "M50-3930342" FP-M50-3930342_HDR3-MFG 47.76,757.43 r270 top
J4 "M50-3930342" FP-M50-3930342_HDR3-MFG 47.76,520.09 r270 top
J5 "105017-0001" CONN_105017-0001 2055.12,-106.96 r90 top
J6 "QSH-030-01-L-D-A" Samtec_QSH-030-01-X-D-A 1219.74,-77.86 r270 bottom locked
L1 "MPZ2012S101A" MPZ2012 1087.23,785.81 r270 bottom
L2 "MPZ2012S101A" MPZ2012 1171.01,1994.6 r0 bottom
L3 "MPZ2012S101A" MPZ2012 999.54,1700.28 r0 bottom
L4 "MCKK2012TR47M" "FP-MCKK2012TR47M_0805 (2012 Metric)-IPC_C" 904.85,127.26 r90 top
L5 "MCKK2012TR47M" "FP-MCKK2012TR47M_0805 (2012 Metric)-IPC_C" 1104.7,126.22 r90 top
L6 "MCKK2012TR47M" "FP-MCKK2012TR47M_0805 (2012 Metric)-IPC_C" 885.96,526.06 r270 top
L7 "MPZ2012S101A" MPZ2012 595.47,1801.73 r0 bottom
L8 "MCKK2012TR47M" "FP-MCKK2012TR47M_0805 (2012 Metric)-IPC_C" 1097.25,525.39 r270 top
L9 "BLM15PD300SZ1D" 0402L 1940.16,-191.63 r270 top
L10 "BLM15PD300SZ1D" 0402L 1694.33,297.06 r90 top
L11 "BLM15PD300SZ1D" 0402L 1937.18,111.24 r0 top
L12 "BLM15PD300SZ1D" 0402L 864.11,33.63 r0 top
LBL1 "THT-14-423-10" Label_650x200 342.38,1727.14 r90 top
Logo1 "Texas Instruments" TI_Stacked_Overlay_Small 1726.87,728.81 r0 top
Logo2 "CE Mark" CE_Mark_5mm 1000.93,207.61 r180 bottom
LOGO3 "FCC disclaimer" FCC_disclaimer 966.67,2181.36 r180 bottom (schematic designator Logo3)
Logo4 "WEEE logo" WEEE_Minimum 1823.8,225.64 r180 bottom
Logo5 "Texas Instruments" TI_Symbol_Overlay_Small 1839.14,-195.13 r180 bottom
Q1 "BSS123-7-F" FP-BSS123-7-F_SOT23-IPC_C 434.95,1130.26 r180 top
Q2 "BSS123" SOT-23 658.67,17.66 r180 top
R1 "MCT06030Z0000ZP500" 0603 1404.27,1630.9 r0 bottom
R2 "CRCW040210K0FKED" 0402L 1215.81,505.56 r90 top
R3 "ERJ-2GE0R00X" 0402 415.17,203.79 r0 bottom
R4 "CRCW02010000Z0ED" 0201_Silk 1424.97,615.63 r180 bottom
R5 "CRCW02010000Z0ED" 0201_Silk 1425.43,507.55 r0 bottom
R6 "CRCW02010000Z0ED" 0201_Silk 1425.43,576.84 r180 bottom
R7 "CRCW02010000Z0ED" 0201_Silk 1614.76,626.86 r0 top
R8 "CRCW02010000Z0ED" 0201_Silk 1425.43,542.19 r180 bottom
R9 "CRCW02010000Z0ED" 0201_Silk 1443.74,650 r0 bottom
R10 "CRCW02010000Z0ED" 0201_Silk 1844.67,642.24 r180 top
R11 "CRCW02010000Z0ED" 0201_Silk 1614.76,666.94 r0 top
R12 "CRCW02010000Z0ED" 0201_Silk 1614.76,707.02 r180 top
R13 "CRCW02010000Z0ED" 0201_Silk 1932.36,659.47 r0 bottom
R14 "CRCW040210K0FKED" 0402L 1301.47,524.81 r270 bottom
R15 "CRCW020120R0FNED" 0201_033 1889.86,606.18 r0 top
R16 "CRCW02010000Z0ED" 0201_Silk 1964.4,801.14 r90 bottom
R17 "CRCW020120R0FNED" 0201_033 1889.86,567.81 r0 top
R18 "CRCW020120R0FNED" 0201_033 1614.76,747.1 r0 top
R19 "CRCW020120R0FNED" 0201_033 1448.74,717.75 r0 bottom
R20 "CRCW020120R0FNED" 0201_033 1383.28,733.93 r0 bottom
R21 "CRCW020120R0FNED" 0201_033 1614.76,787.18 r0 top
R22 "CRCW02010000Z0ED" 0201_Silk 1863.79,744.08 r180 top
R23 "CRCW020120R0FNED" 0201_033 1443.74,753.93 r0 bottom
R24 "CRCW02010000Z0ED" 0201_Silk 1863.79,779.08 r180 top
R25 "CRCW02010000Z0ED" 0201 1229.01,617.73 r90 top
R26 "CRCW020120R0FNED" 0201_033 1443.74,788.57 r0 bottom
R27 "CRCW020120R0FNED" 0201_033 1448.74,823.21 r0 bottom
R28 "CRCW020120R0FNED" 0201_033 1448.74,857.86 r0 bottom
R29 "CRCW02010000Z0ED" 0201 1267.18,617.73 r90 top
R30 "CRCW02010000Z0ED" 0201_Silk 1863.79,828.55 r180 top
R31 "CRCW02010000Z0ED" 0201_Silk 1932.36,697.17 r0 bottom
R32 "CRCW02010000Z0ED" 0201_Silk 1863.79,863.55 r180 top
R33 "CRCW02010000Z0ED" 0201_Silk 1863.79,923.9 r180 top
R34 "CRCW02010000Z0ED" 0201_Silk 1475,1113.43 r0 bottom
R35 "CRCW02010000Z0ED" 0201_Silk 1863.79,961.88 r180 top
R36 "CRCW02010000Z0ED" 0201_Silk 1845.35,680.05 r180 top
R37 "CRCW02010000Z0ED" 0201_Silk 1515,1147.43 r0 bottom
R38 "CRCW02010000Z0ED" 0201_Silk 1704.94,1250.43 r180 bottom
R39 "CRCW02010000Z0ED" 0201_Silk 1863.79,1026.09 r180 top
R40 "CRCW02010000Z0ED" 0201_Silk 1704.94,1288.81 r180 bottom
R41 "CRCW02010000Z0ED" 0201_Silk 1863.79,1064.07 r180 top
R42 "CRCW02010000Z0ED" 0201_Silk 1932.38,621.93 r180 bottom
R43 "ERJ-2GE0R00X" 0402 553.88,546.45 r270 top
R44 "CRCW040210K0FKED" 0402L 418.88,981.89 r90 top
R45 "CRCW020133R2FNED" 0201_Silk 403.88,538.85 r270 top
R46 "CRCW020133R2FNED" 0201_Silk 503.88,902.76 r270 top
R47 "CRCW020133R2FNED" 0201_Silk 453.88,902.76 r270 top
R48 "CRCW020133R2FNED" 0201_Silk 453.88,538.85 r270 top
R49 "CRCW040210K0FKED" 0402L 512.82,478.51 r0 top
R50 "CRCW040247K5FKED" 0402L 553.88,903.85 r270 top
R51 "CRCW020133R2FNED" 0201_Silk 503.88,538.85 r270 top locked
R52 "CRCW040210K0FKED" 0402L 809.93,671.77 r0 bottom
R53 "CRCW040210K0FKED" 0402L 768.74,801.43 r90 bottom
R54 "CRCW040210K0FKED" 0402L 943.74,831.43 r90 bottom
R55 "CRCW02010000Z0ED" 0201 839.48,712.79 r0 bottom
R56 "CRCW02010000Z0ED" 0201 843.74,786.43 r0 bottom
R57 "CRCW04020000Z0ED" 0402 990.93,587.76 r270 bottom
R58 "CRCW02010000Z0ED" 0201_Silk 1931.3,1008.12 r0 bottom
R59 "CRCW02010000Z0ED" 0201_Silk 1931.3,1046.36 r0 bottom
R60 "CRCW02010000Z0ED" 0201_Silk 1448.74,892.5 r180 bottom
R61 "CRCW02010000Z0ED" 0201_Silk 1448.74,927.14 r180 bottom
R62 "CRCW02010000Z0ED" 0201_Silk 1448.74,961.79 r180 bottom
R63 "CRCW02010000Z0ED" 0201_Silk 1448.74,996.43 r180 bottom
R64 "CRCW02010000Z0ED" 0201_Silk 1475,1079.43 r180 bottom
R65 "CRCW02010000Z0ED" 0201_Silk 1980,1251.43 r270 bottom
R66 "CRCW02010000Z0ED" 0201_Silk 1945,1251.43 r90 bottom
R67 "CRCW02010000Z0ED" 0201_Silk 1910,1251.43 r90 bottom
R68 "CRCW040261R9FKED" 0402L 243.19,306.93 r0 bottom
R69 "CRCW02010000Z0ED" 0201_Silk 330.22,348.06 r270 bottom
R70 "CRCW040210K0FKED" 0402L 411.23,251.6 r180 bottom
R71 "CRCW040210K0FKED" 0402L 411.23,285.9 r0 bottom
R72 "ERJ-2GE0R00X" 0402 782.12,1618.43 r0 top
R73 "ERJ-2GE0R00X" 0402 810.31,1567.75 r0 top
R74 "ERJ-2GE0R00X" 0402 800.59,1506.43 r0 top
R75 "ERJ-2GE0R00X" 0402 704.13,1557.21 r0 top
R76 "ERJ-2GE0R00X" 0402 1490,961.43 r90 top
R77 "ERJ-2GE0R00X" 0402 1268.74,821.43 r180 top
R78 "ERJ-2GE0R00X" 0402 528.88,281.56 r90 bottom
R79 "CRCW040261R9FKED" 0402L 243.19,350.05 r180 bottom
R80 "ERJ-2GE0R00X" 0402 538.88,281.56 r90 top
R81 "CRCW040261R9FKED" 0402L 100.49,69.38 r180 bottom
R82 "CRCW02010000Z0ED" 0201_Silk 201.99,142.09 r270 bottom
R83 "CRCW040210K0FKED" 0402L 559.05,76.66 r270 top
R84 "CRCW040210K0FKED" 0402L 474.08,76.66 r90 top
R85 "ERJ-2GE0R00X" 0402 404.57,60.08 r180 top
R86 "CRCW040261R9FKED" 0402L 100.49,169.38 r0 bottom
R87 "ERJ-2GE0R00X" 0402 404.57,205.08 r180 top
R88 "CRCW040210K0FKED" 0402L 638.24,416.35 r90 top
R89 "CRCW04024K70JNED" 0402 755.42,386.89 r270 top
R90 "RC0201FR-074K99L" 0201L 1789.23,99.82 r180 top
R91 "RC0201JR-070RL" "FP-RC0201JR-070RL_0201 (0603 Metric)-MFG" 1936.18,-81.82 r0 top
R92 "RC0201JR-070RL" "FP-RC0201JR-070RL_0201 (0603 Metric)-MFG" 1936.18,-108.48 r0 top
R93 "RC0201FR-074K99L" 0201L 1702.37,110.34 r270 top
R94 "CRCW040210K0FKED" 0402L 1303.87,624.42 r270 top
R95 "RR0306P-103-D" FP-RR0306P-103-D_0201-IPC_C 1750.79,110.34 r270 top
R96 "RC0201JR-070RL" "FP-RC0201JR-070RL_0201 (0603 Metric)-MFG" 1693.49,-163.08 r180 top
R97 "RC0201JR-070RL" "FP-RC0201JR-070RL_0201 (0603 Metric)-MFG" 1594.83,43.03 r180 top
R98 "RC0201JR-070RL" "FP-RC0201JR-070RL_0201 (0603 Metric)-MFG" 1594.83,13.91 r0 top
R99 "RC0201JR-07220RL" 0201L 1615.28,-124.7 r180 top
R100 "RR0306P-103-D" FP-RR0306P-103-D_0201-IPC_C 1922.81,359.82 r0 top
R101 "CRCW040210K0FKED" 0402L 1182.13,505.53 r270 top
R102 "RR0306P-103-D" FP-RR0306P-103-D_0201-IPC_C 1397.73,274.12 r0 top
R103 "CRCW040210K0FKED" 0402L 1266.47,524.81 r90 bottom
R104 "CRCW040210K0FKED" 0402L 378.85,1558.68 r180 bottom
R105 "CRCW040210K0FKED" 0402L 378.85,1525.06 r180 bottom
R106 "CRCW040210K0FKED" 0402L 634.64,418.02 r180 bottom
R107 "CRCW040210K0FKED" 0402L 674.01,336.97 r0 bottom
R108 "CRCW02010000Z0ED" 0201 458.56,1752.5 r90 bottom
R109 "CRCW02010000Z0ED" 0201 715,716.43 r0 bottom
R110 "CRCW02010000Z0ED" 0201 497.17,1752.5 r90 bottom
R111 "CRCW02010000Z0ED" 0201 715,681.43 r0 bottom
R112 "CRCW040210K0FKED" 0402L 378.85,1653.12 r0 bottom
R113 "CRCW040210K0FKED" 0402L 378.85,1592.31 r0 bottom
R114 "CRCW040210K0FKED" 0402L 378.85,1491.43 r0 bottom
R115 "CRCW040210K0FKED" 0402L 636.16,695.69 r270 bottom
R116 "CRCW040210K0FKED" 0402L 634.64,454.23 r0 bottom
R117 "CRCW040210K0FKED" 0402L 634.64,381.8 r0 bottom
R118 "RC0201JR-07510RL" 0201L 1521.34,316.41 r180 top
R119 "CRCW0201100KFKED" 0201L 1467.08,285.17 r90 top
R120 "CRCW0201100KFKED" 0201L 1432.23,285.17 r270 top
R121 "CRCW0402200RFKEDHP" FP-CRCW0402200RFKEDHP_0402-IPC_C 1438.41,169.94 r0 top
R122 "ERJ-2GE0R00X" 0402L 729.49,-47.51 r0 bottom
R123 "RR0306P-103-D" FP-RR0306P-103-D_0201-IPC_C 622.73,1016.99 r180 top
R124 "CRCW020120R0FNED" 0201_033 658.74,1021.43 r180 bottom
R125 "CRCW020120R0FNED" 0201_033 658.74,986.43 r180 bottom
R126 "CRCW020120R0FNED" 0201_033 643.74,951.43 r180 bottom
R127 "CRCW020120R0FNED" 0201_033 643.74,916.43 r180 bottom
R128 "CRCW020120R0FNED" 0201_033 643.74,881.43 r180 bottom
R129 "CRCW020120R0FNED" 0201_033 643.74,851.43 r180 bottom
R130 "CRCW020120R0FNED" 0201_033 643.74,816.43 r180 bottom
R131 "CRCW02010000Z0ED" 0201_Silk 260,890.5 r0 top
R132 "CRCW020120R0FNED" 0201_033 643.74,781.43 r180 bottom
R133 "CRCW02010000Z0ED" 0201_Silk 260,855.5 r0 top
R134 "CRCW02010000Z0ED" 0201_Silk 260,804.68 r0 top
R135 "CRCW02010000Z0ED" 0201_Silk 260,769.68 r0 top
R136 "CRCW02010000Z0ED" 0201_Silk 260,696.43 r0 top
R137 "CRCW02010000Z0ED" 0201_Silk 260,661.43 r0 top
R138 "RR0306P-103-D" FP-RR0306P-103-D_0201-IPC_C 622.73,1065.29 r180 top
R139 "CRCW040210K0FKED" 0402L 955.18,1416.6 r90 bottom
R140 "CRCW02010000Z0ED" 0201_Silk 658.74,1056.43 r180 bottom
R141 "RC0201JR-07510RL" 0201L 302.97,1105.85 r270 top
R142 "CRCW040210K0FKED" 0402L 965,1336.43 r0 bottom
R143 "CRCW02010000Z0ED" 0201 883.92,1416.6 r90 bottom
R144 "CRCW02010000Z0ED" 0201 833.74,1416.43 r90 bottom
R145 "CRCW040210K0FKED" 0402L 798.74,1416.43 r270 bottom
R146 "CRCW040210K0FKED" 0402L 920.18,1416.6 r270 bottom
R147 "CRCW040210K0FKED" 0402L 965,1301.43 r180 bottom
R148 "CRCW020120R0FNED" 0201_033 1196.94,160.87 r270 bottom
R149 "CRCW020120R0FNED" 0201_033 1234.31,160.87 r270 bottom
R150 "CRCW040210K0JNED" 0402 1900,1119.34 r180 top
R151 "CRCW04020000Z0ED" 0402 977.93,695.88 r270 bottom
